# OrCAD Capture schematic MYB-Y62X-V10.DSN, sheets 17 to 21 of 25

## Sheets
17 PAGE18 - USB2.0 HUB #: size A2; note: USB I/F
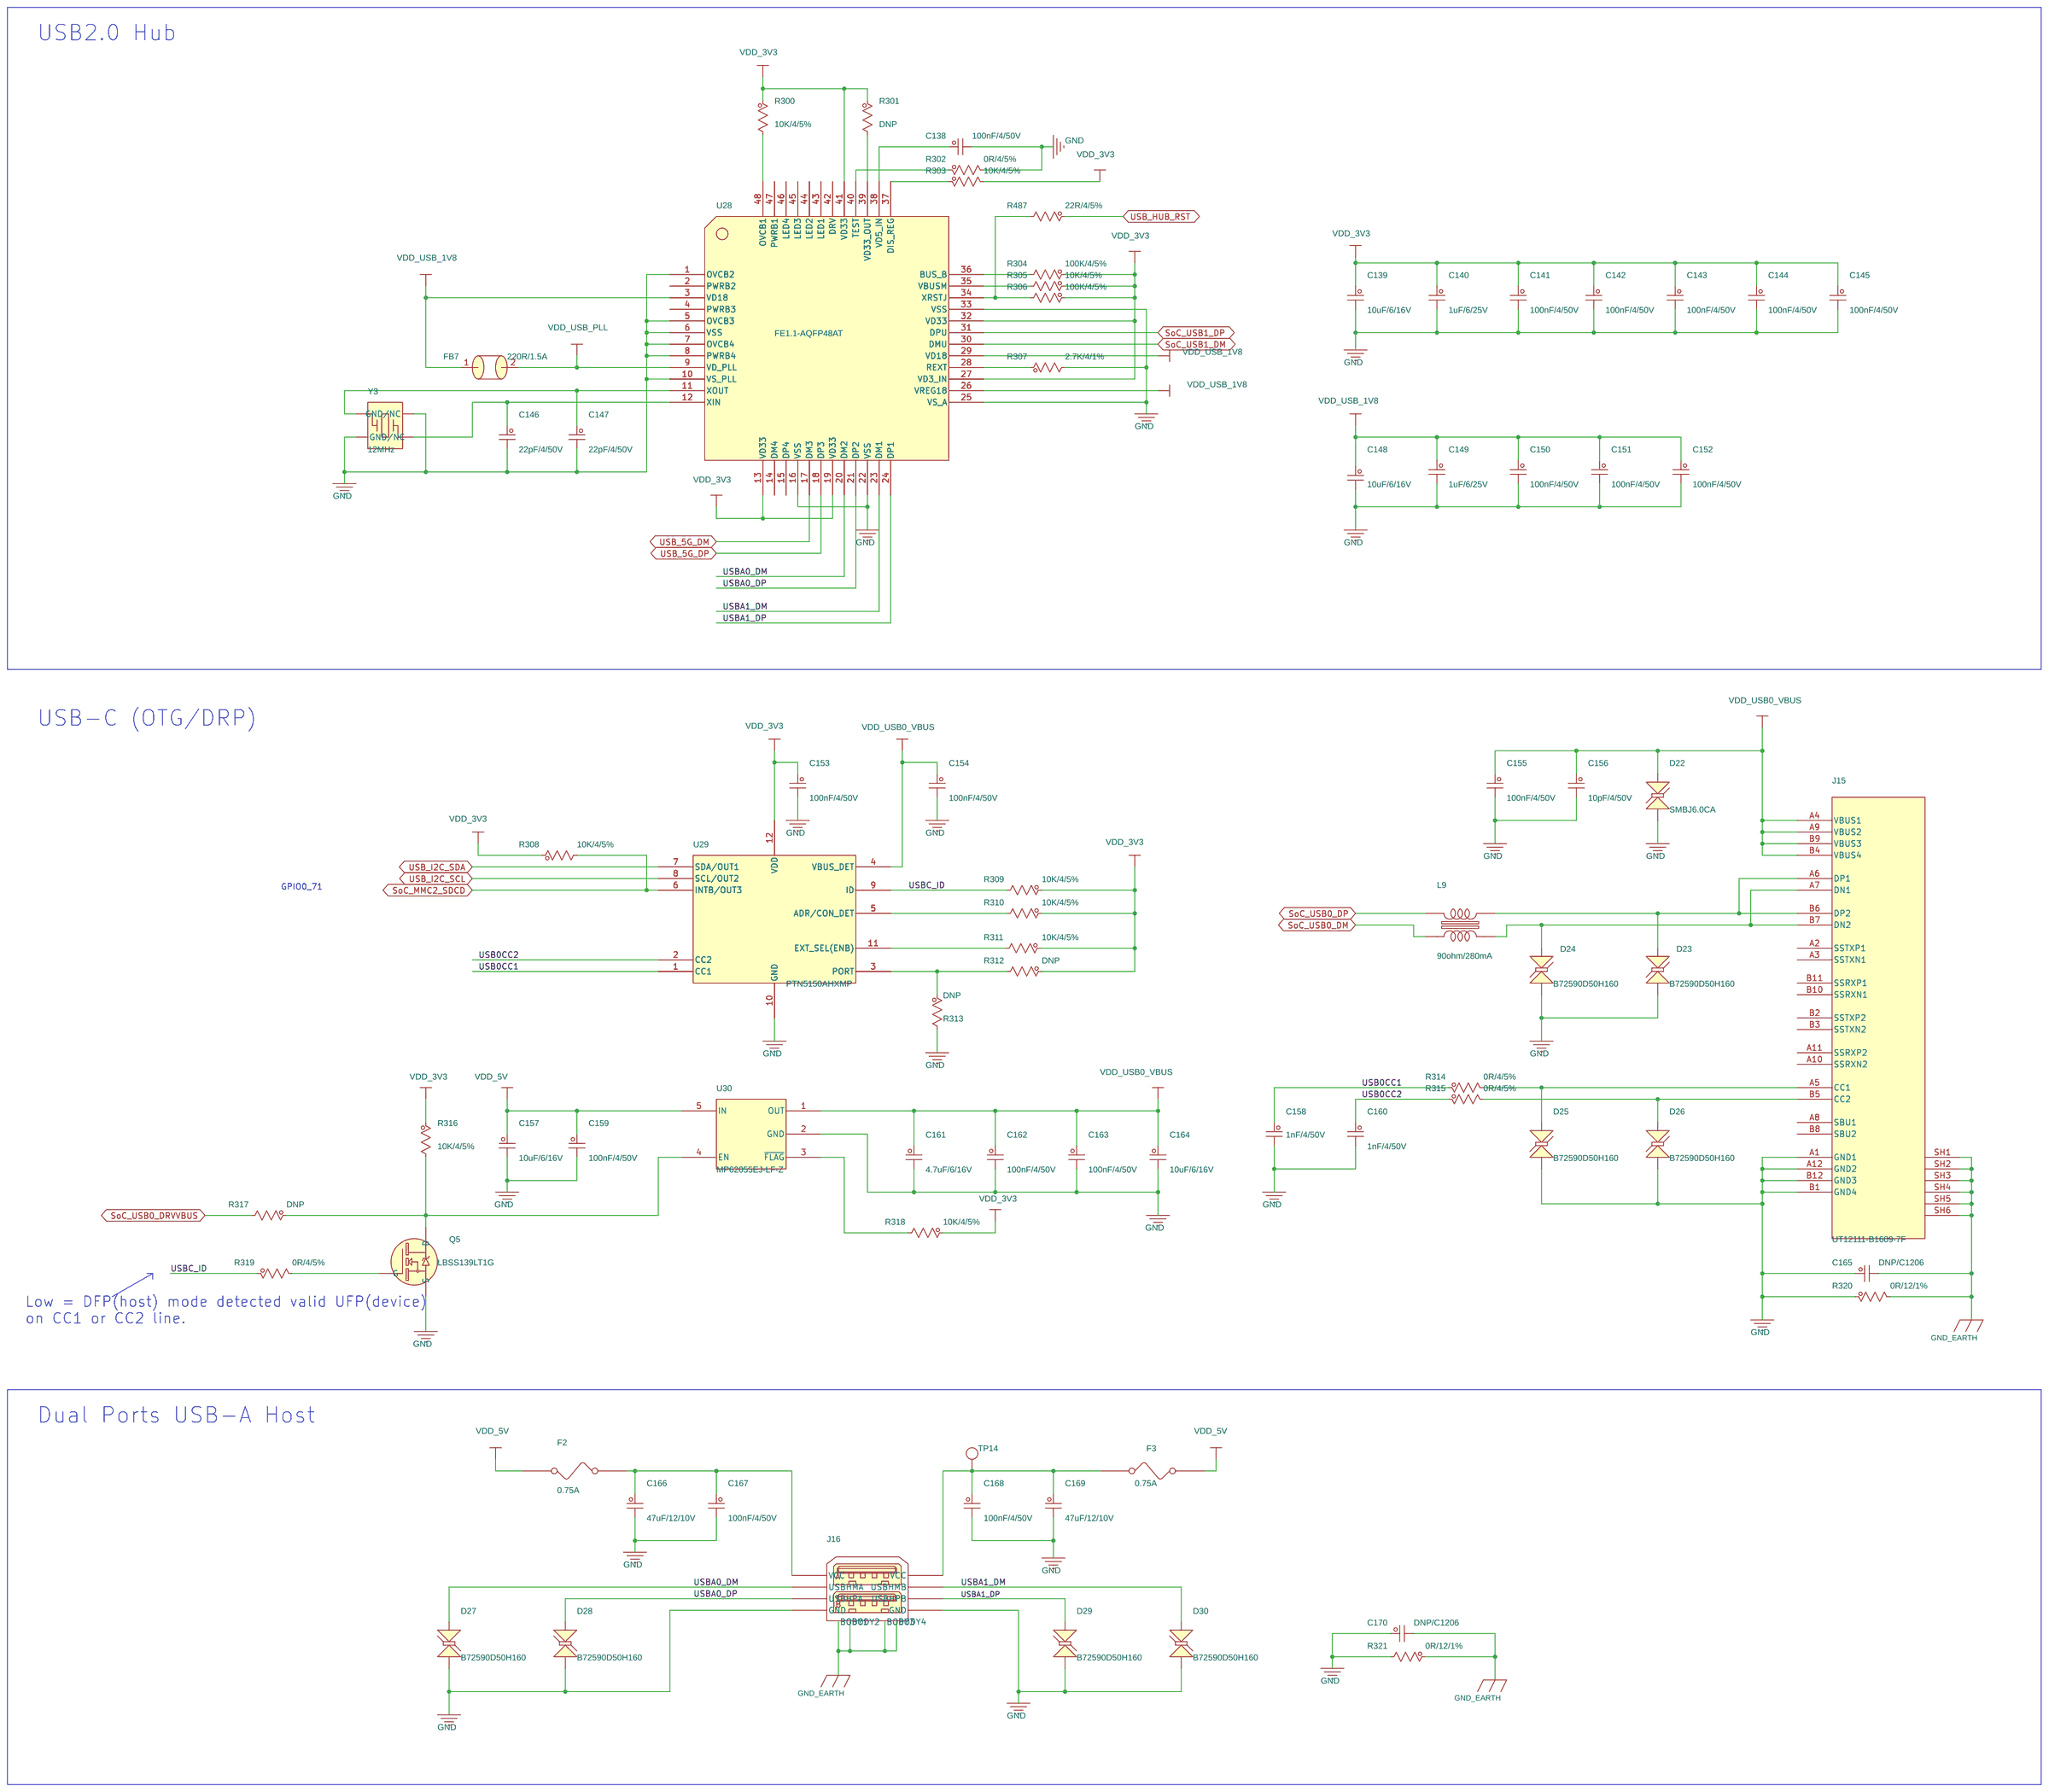
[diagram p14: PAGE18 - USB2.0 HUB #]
18 PAGE20 - RGMII_1 ETHERNET PHY #: size C; note: RGMII_1 ETHERNET PHY
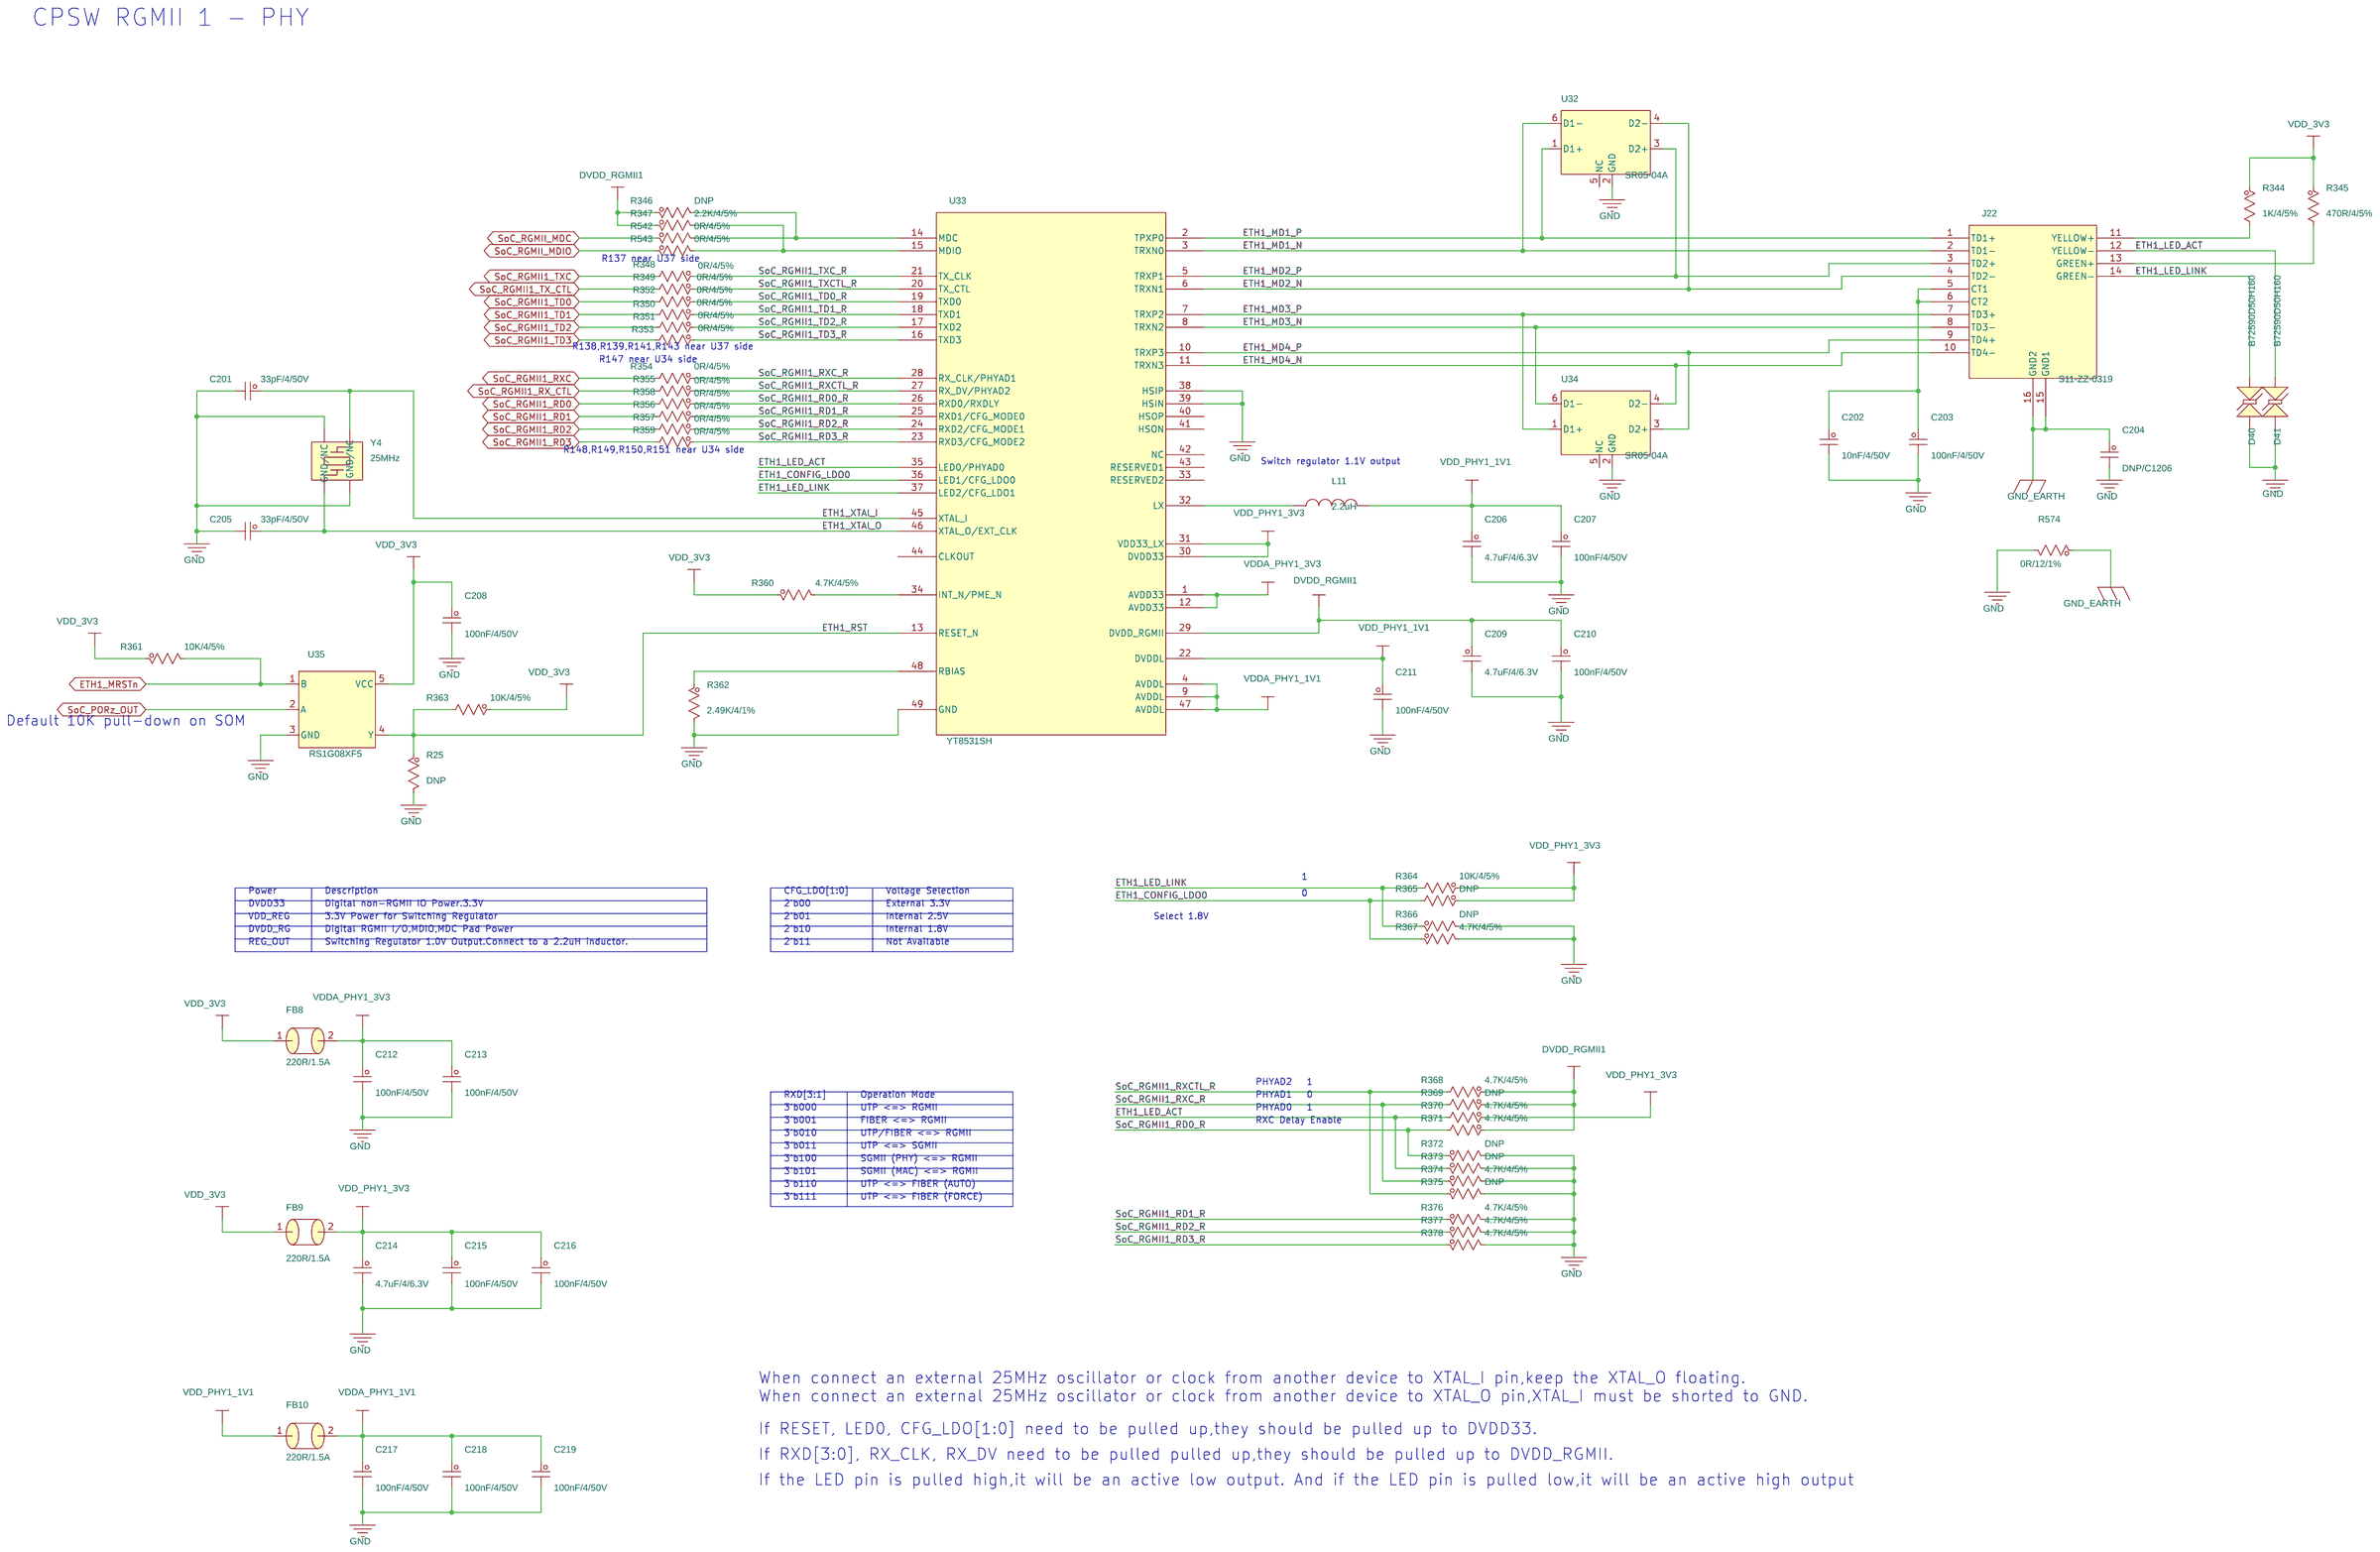
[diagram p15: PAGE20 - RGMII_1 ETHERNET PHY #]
19 PAGE21 - RGMII_2 ETHERNET PHY #: size C; note: RGMII_2 ETHERNET PHY
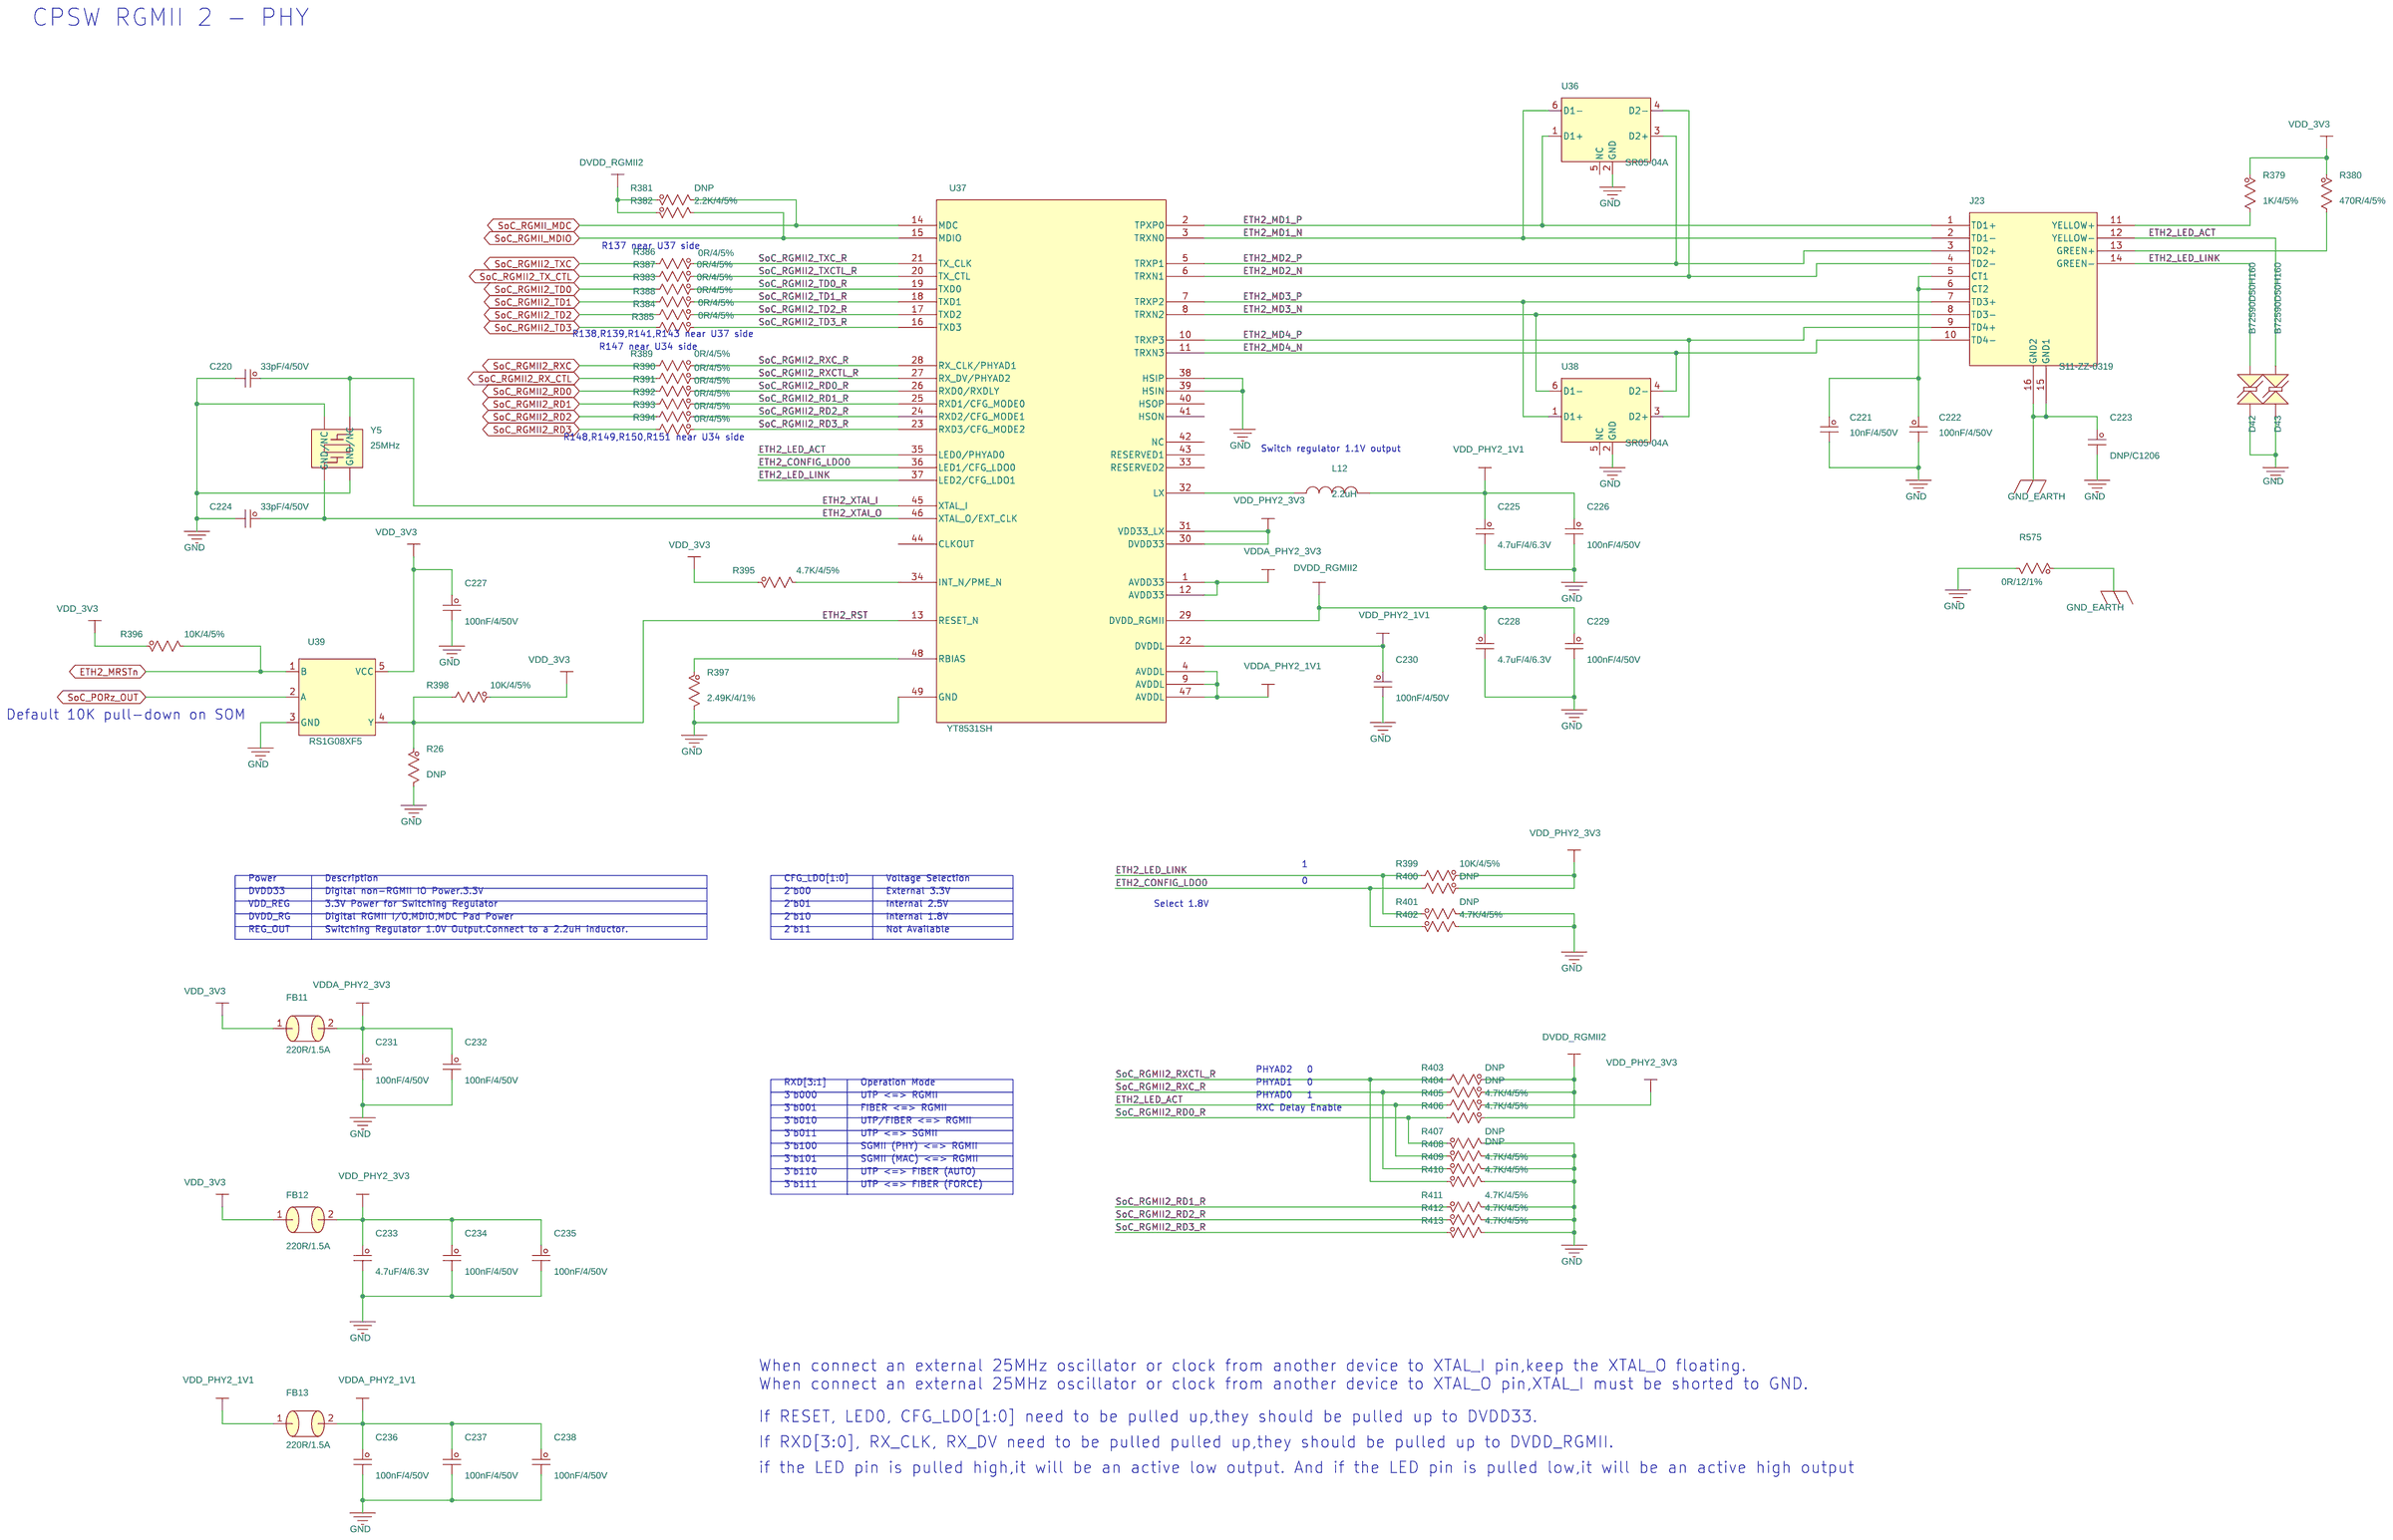
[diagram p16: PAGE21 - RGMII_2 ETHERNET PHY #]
20 PAGE22 - KEY & RTC #: size A3; note: KEY & RTC & PH-RPI
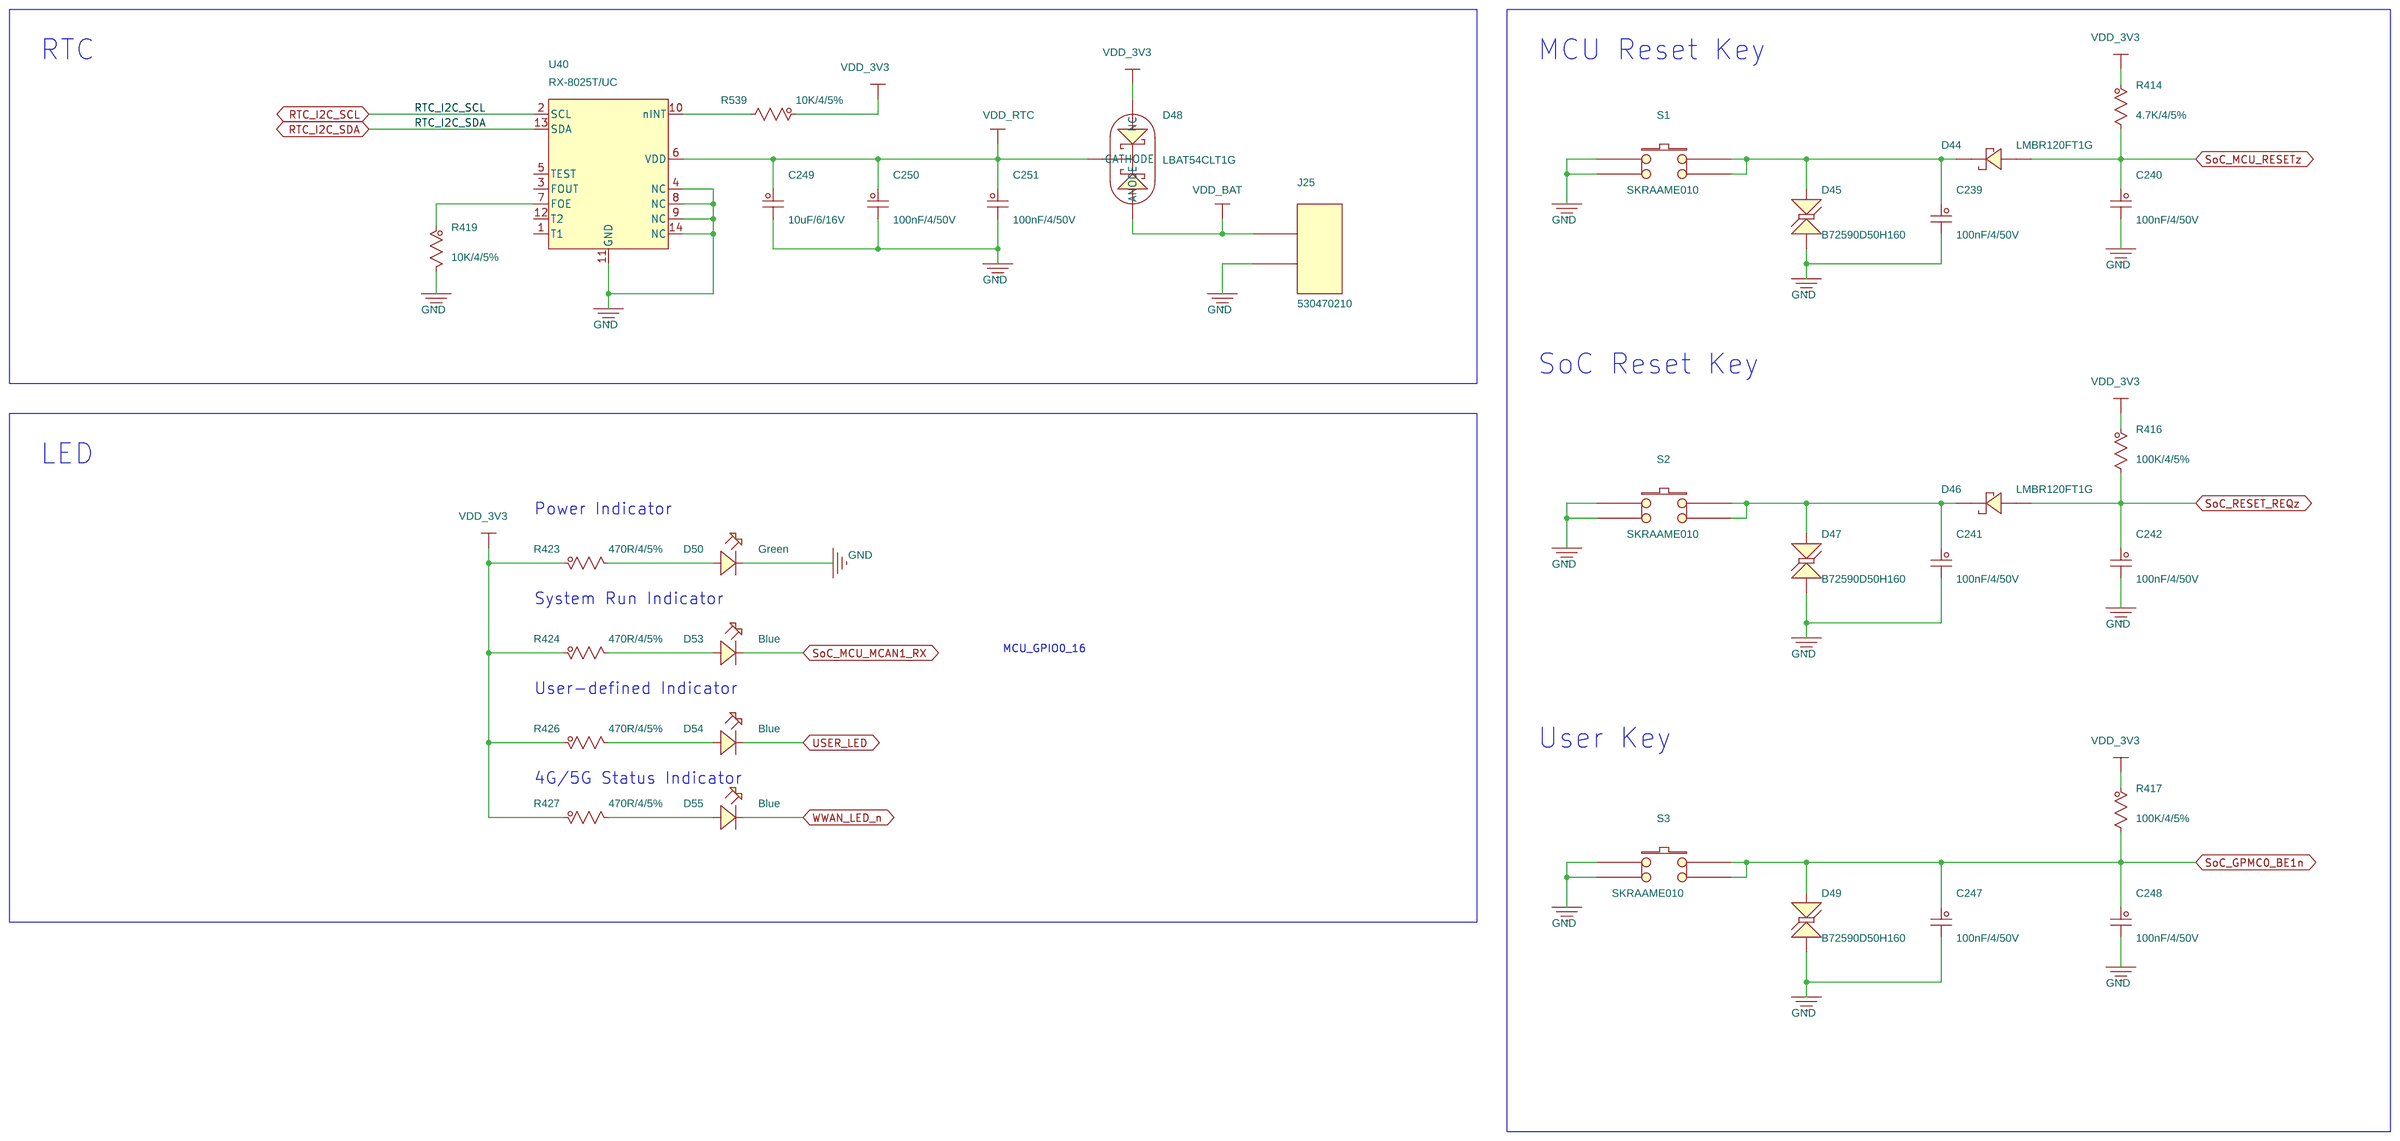
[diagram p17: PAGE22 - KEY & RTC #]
21 PAGE23 - IO EXPANDER #: size C; note: IO EXPANDER
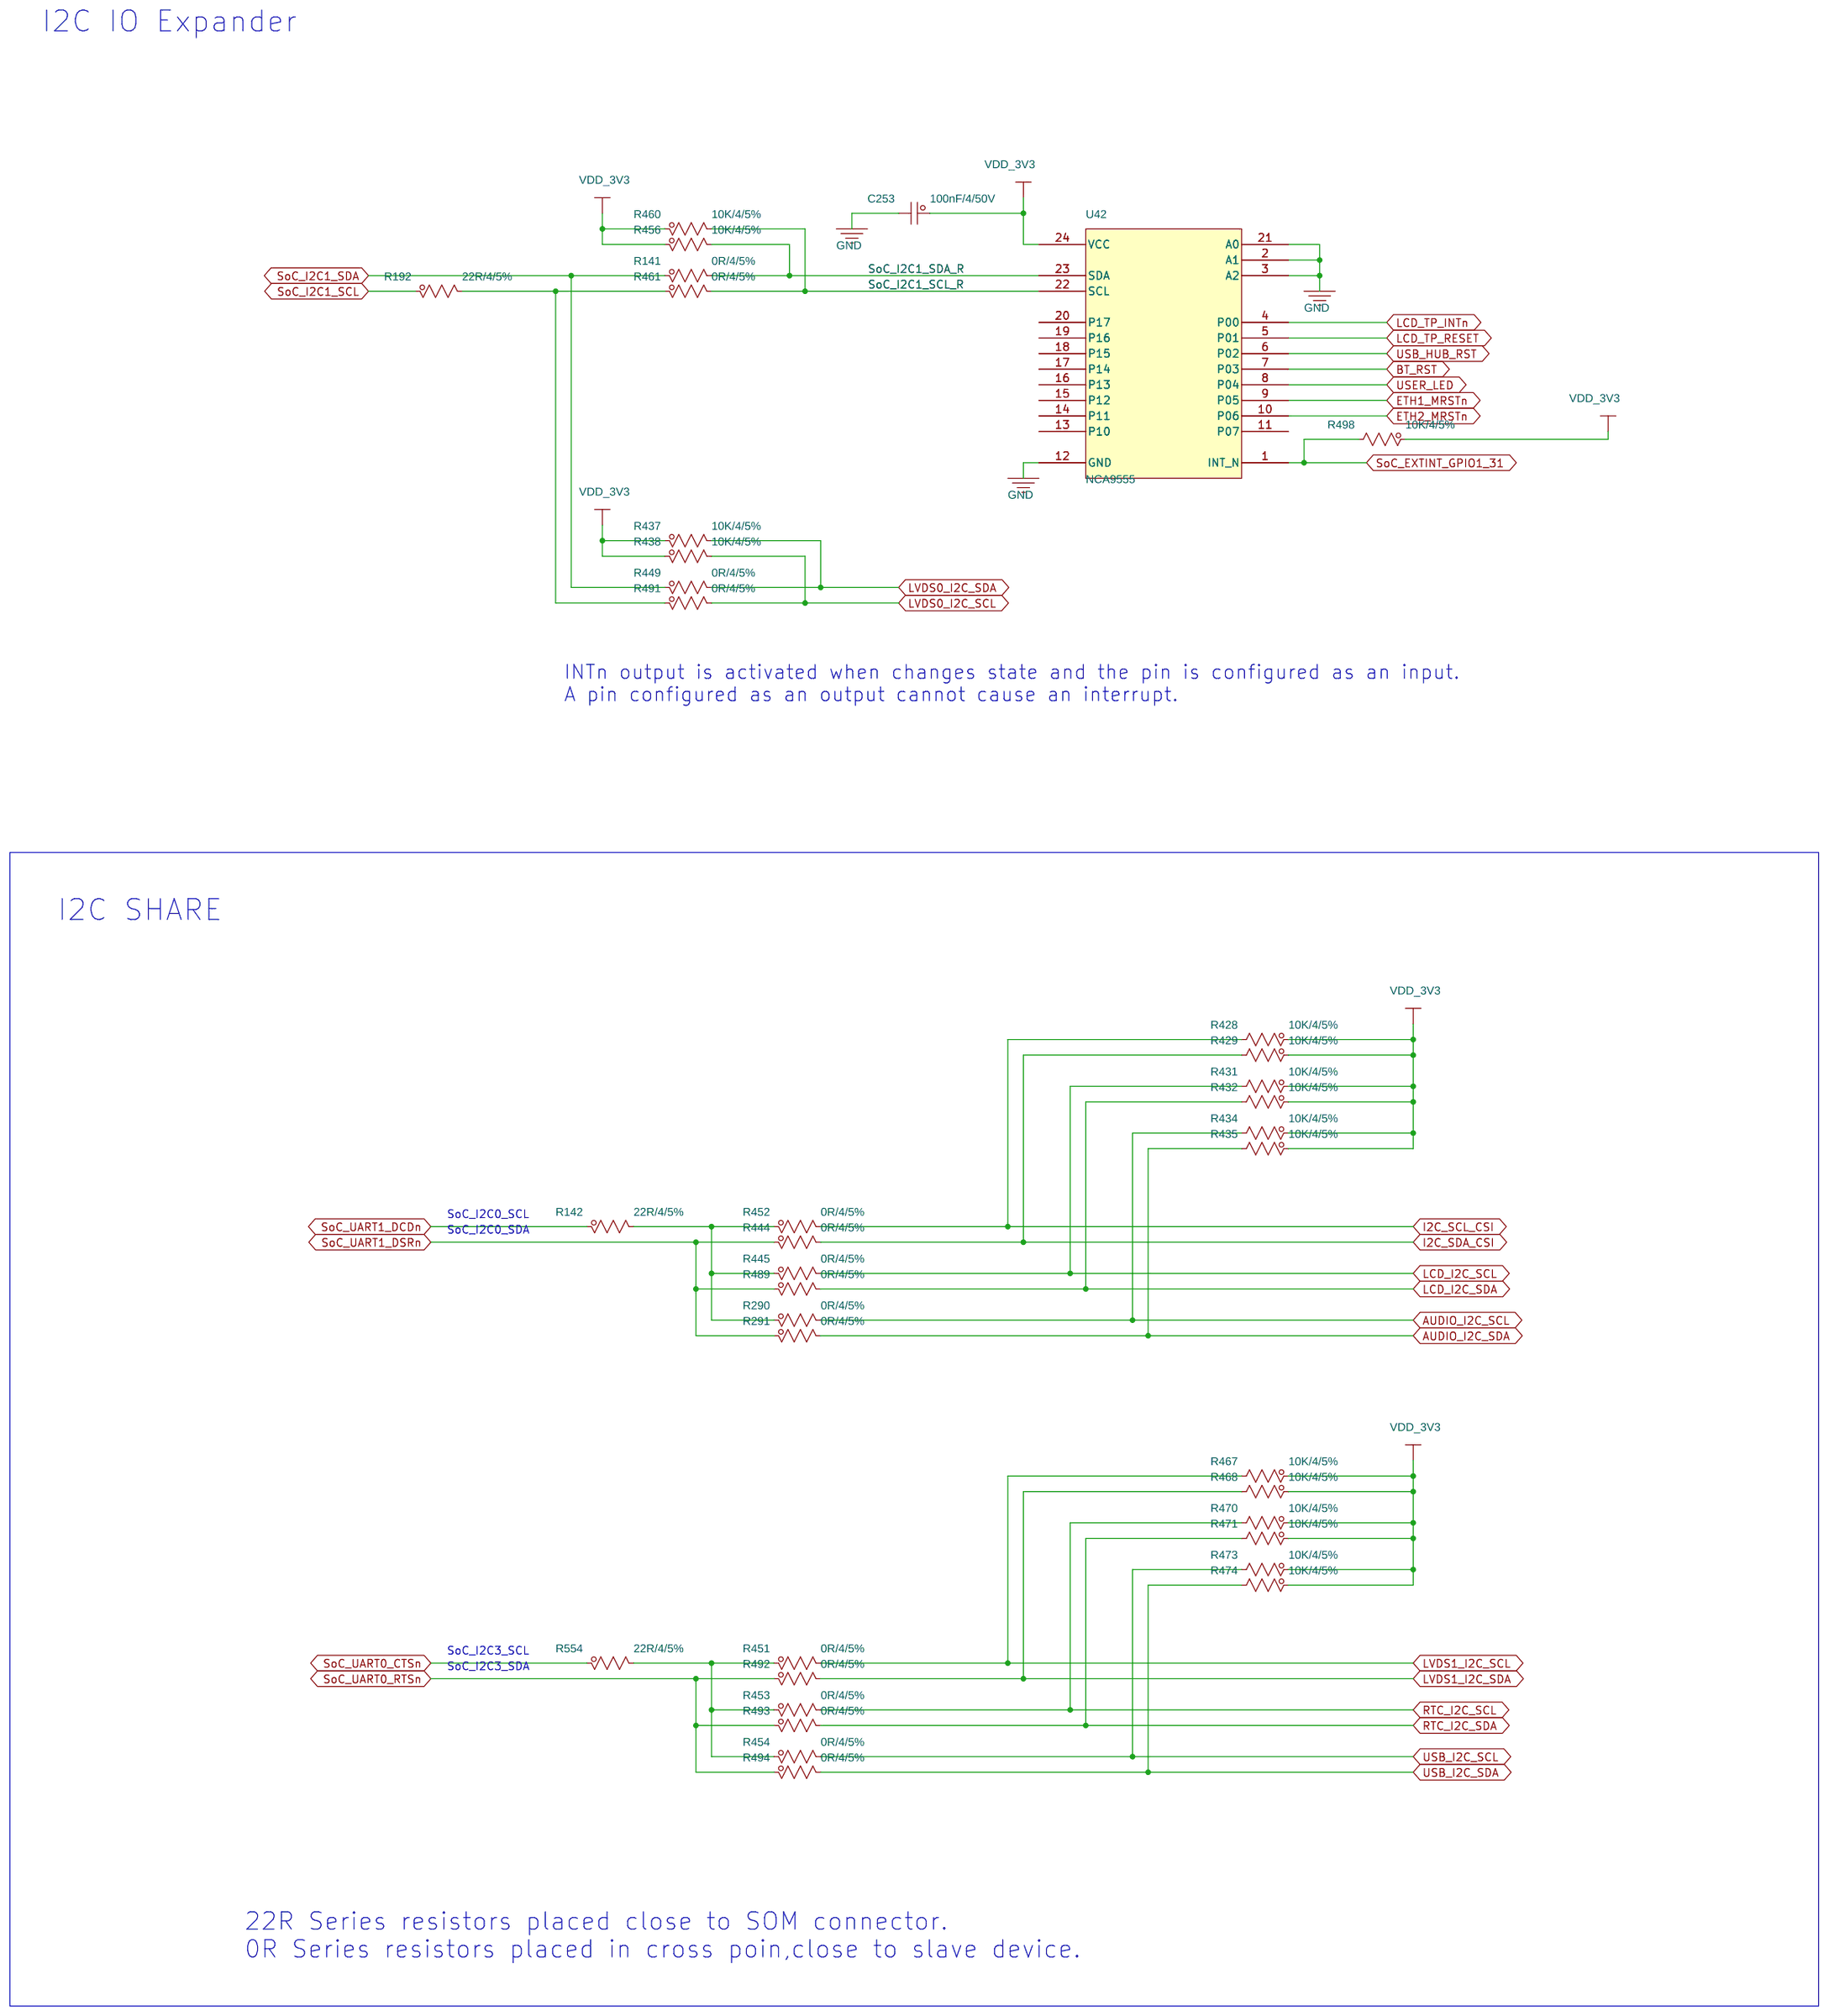
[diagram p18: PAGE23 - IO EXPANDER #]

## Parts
sheet PAGE18 - USB2.0 HUB #
C138  100nF/4/50V  [C0402]
C139  10uF/6/16V  [C0603]
C140  1uF/6/25V  [C0603]
C141  100nF/4/50V  [C0402]
C142  100nF/4/50V  [C0402]
C143  100nF/4/50V  [C0402]
C144  100nF/4/50V  [C0402]
C145  100nF/4/50V  [C0402]
C146  22pF/4/50V  [C0402]
C147  22pF/4/50V  [C0402]
C148  10uF/6/16V  [C0603]
C149  1uF/6/25V  [C0603]
C150  100nF/4/50V  [C0402]
C151  100nF/4/50V  [C0402]
C152  100nF/4/50V  [C0402]
C153  100nF/4/50V  [C0402]
C154  100nF/4/50V  [C0402]
C155  100nF/4/50V  [C0402]
C156  10pF/4/50V  [C0402]
C157  10uF/6/16V  [C0603]
C158  1nF/4/50V  [C0402]
C159  100nF/4/50V  [C0402]
C160  1nF/4/50V  [C0402]
C161  4.7uF/6/16V  [C0603]
C162  100nF/4/50V  [C0402]
C163  100nF/4/50V  [C0402]
C164  10uF/6/16V  [C0603]
C165  DNP/C1206  [C1206]
C166  47uF/12/10V  [C1206]
C167  100nF/4/50V  [C0402]
C168  100nF/4/50V  [C0402]
C169  47uF/12/10V  [C1206]
C170  DNP/C1206  [C1206]
D22  SMBJ6.0CA  [DO-214AA]
D23  B72590D50H160  [D0402]
D24  B72590D50H160  [D0402]
D25  B72590D50H160  [D0402]
D26  B72590D50H160  [D0402]
D27  B72590D50H160  [D0402]
D28  B72590D50H160  [D0402]
D29  B72590D50H160  [D0402]
D30  B72590D50H160  [D0402]
F2  0.75A  [F1206]
F3  0.75A  [F1206]
FB7  220R/1.5A  [FB0603]
J15  UT12111-B1609-7F  [UT12111-B1609-7F]
J16  UB11121-8FDE-4F  [UB11121-8FDE-4F]
L9  90ohm/280mA  [indcm-sdcw2012]
Q5  LBSS139LT1G  [SOT-23]
R300  10K/4/5%  [R0402]
R301  DNP  [R0402]
R302  0R/4/5%  [R0402]
R303  10K/4/5%  [R0402]
R304  100K/4/5%  [R0402]
R305  10K/4/5%  [R0402]
R306  100K/4/5%  [R0402]
R307  2.7K/4/1%  [R0402]
R308  10K/4/5%  [R0402]
R309  10K/4/5%  [R0402]
R310  10K/4/5%  [R0402]
R311  10K/4/5%  [R0402]
R312  DNP  [R0402]
R313  DNP  [R0402]
R314  0R/4/5%  [R0402]
R315  0R/4/5%  [R0402]
R316  10K/4/5%  [R0402]
R317  DNP  [R0402]
R318  10K/4/5%  [R0402]
R319  0R/4/5%  [R0402]
R320  0R/12/1%  [R1206]
R321  0R/12/1%  [R1206]
R487  22R/4/5%  [R0402]
TP14  SMD  [test0_8-smd]
U28  FE1.1-AQFP48AT  [LQFP48]
U29  PTN5150AHXMP  [x2qfn12]
U30  MP62055EJ-LF-Z  [SOT23-5]
Y3  12MHz  [3225]
sheet PAGE20 - RGMII_1 ETHERNET PHY #
C201  33pF/4/50V  [C0402]
C202  10nF/4/50V  [C0402]
C203  100nF/4/50V  [C0402]
C204  DNP/C1206  [C1206]
C205  33pF/4/50V  [C0402]
C206  4.7uF/4/6.3V  [C0402]
C207  100nF/4/50V  [C0402]
C208  100nF/4/50V  [C0402]
C209  4.7uF/4/6.3V  [C0402]
C210  100nF/4/50V  [C0402]
C211  100nF/4/50V  [C0402]
C212  100nF/4/50V  [C0402]
C213  100nF/4/50V  [C0402]
C214  4.7uF/4/6.3V  [C0402]
C215  100nF/4/50V  [C0402]
C216  100nF/4/50V  [C0402]
C217  100nF/4/50V  [C0402]
C218  100nF/4/50V  [C0402]
C219  100nF/4/50V  [C0402]
D40  B72590D50H160  [D0402]
D41  B72590D50H160  [D0402]
FB8  220R/1.5A  [FB0603]
FB9  220R/1.5A  [FB0603]
FB10  220R/1.5A  [FB0603]
J22  S11-ZZ-0319  [S11-ZZ-0319]
L11  2.2uH  [L3X3]
R25  DNP  [R0402]
R344  1K/4/5%  [R0402]
R345  470R/4/5%  [R0402]
R346  DNP  [R0402]
R347  2.2K/4/5%  [R0402]
R348  0R/4/5%  [R0402]
R349  0R/4/5%  [R0402]
R350  0R/4/5%  [R0402]
R351  0R/4/5%  [R0402]
R352  0R/4/5%  [R0402]
R353  0R/4/5%  [R0402]
R354  0R/4/5%  [R0402]
R355  0R/4/5%  [R0402]
R356  0R/4/5%  [R0402]
R357  0R/4/5%  [R0402]
R358  0R/4/5%  [R0402]
R359  0R/4/5%  [R0402]
R360  4.7K/4/5%  [R0402]
R361  10K/4/5%  [R0402]
R362  2.49K/4/1%  [R0402]
R363  10K/4/5%  [R0402]
R364  10K/4/5%  [R0402]
R365  DNP  [R0402]
R366  DNP  [R0402]
R367  4.7K/4/5%  [R0402]
R368  4.7K/4/5%  [R0402]
R369  DNP  [R0402]
R370  4.7K/4/5%  [R0402]
R371  4.7K/4/5%  [R0402]
R372  DNP  [R0402]
R373  DNP  [R0402]
R374  4.7K/4/5%  [R0402]
R375  DNP  [R0402]
R376  4.7K/4/5%  [R0402]
R377  4.7K/4/5%  [R0402]
R378  4.7K/4/5%  [R0402]
R542  0R/4/5%  [R0402]
R543  0R/4/5%  [R0402]
R574  0R/12/1%  [R1206]
U32  SR05-04A  [SOT23-6]
U33  YT8531SH  [QFN48-0_4]
U34  SR05-04A  [SOT23-6]
U35  RS1G08XF5  [SOT23-5]
Y4  25MHz  [3225]
sheet PAGE21 - RGMII_2 ETHERNET PHY #
C220  33pF/4/50V  [C0402]
C221  10nF/4/50V  [C0402]
C222  100nF/4/50V  [C0402]
C223  DNP/C1206  [C1206]
C224  33pF/4/50V  [C0402]
C225  4.7uF/4/6.3V  [C0402]
C226  100nF/4/50V  [C0402]
C227  100nF/4/50V  [C0402]
C228  4.7uF/4/6.3V  [C0402]
C229  100nF/4/50V  [C0402]
C230  100nF/4/50V  [C0402]
C231  100nF/4/50V  [C0402]
C232  100nF/4/50V  [C0402]
C233  4.7uF/4/6.3V  [C0402]
C234  100nF/4/50V  [C0402]
C235  100nF/4/50V  [C0402]
C236  100nF/4/50V  [C0402]
C237  100nF/4/50V  [C0402]
C238  100nF/4/50V  [C0402]
D42  B72590D50H160  [D0402]
D43  B72590D50H160  [D0402]
FB11  220R/1.5A  [FB0603]
FB12  220R/1.5A  [FB0603]
FB13  220R/1.5A  [FB0603]
J23  S11-ZZ-0319  [S11-ZZ-0319]
L12  2.2uH  [L3X3]
R26  DNP  [R0402]
R379  1K/4/5%  [R0402]
R380  470R/4/5%  [R0402]
R381  DNP  [R0402]
R382  2.2K/4/5%  [R0402]
R383  0R/4/5%  [R0402]
R384  0R/4/5%  [R0402]
R385  0R/4/5%  [R0402]
R386  0R/4/5%  [R0402]
R387  0R/4/5%  [R0402]
R388  0R/4/5%  [R0402]
R389  0R/4/5%  [R0402]
R390  0R/4/5%  [R0402]
R391  0R/4/5%  [R0402]
R392  0R/4/5%  [R0402]
R393  0R/4/5%  [R0402]
R394  0R/4/5%  [R0402]
R395  4.7K/4/5%  [R0402]
R396  10K/4/5%  [R0402]
R397  2.49K/4/1%  [R0402]
R398  10K/4/5%  [R0402]
R399  10K/4/5%  [R0402]
R400  DNP  [R0402]
R401  DNP  [R0402]
R402  4.7K/4/5%  [R0402]
R403  DNP  [R0402]
R404  DNP  [R0402]
R405  4.7K/4/5%  [R0402]
R406  4.7K/4/5%  [R0402]
R407  DNP  [R0402]
R408  DNP  [R0402]
R409  4.7K/4/5%  [R0402]
R410  4.7K/4/5%  [R0402]
R411  4.7K/4/5%  [R0402]
R412  4.7K/4/5%  [R0402]
R413  4.7K/4/5%  [R0402]
R575  0R/12/1%  [R1206]
U36  SR05-04A  [SOT23-6]
U37  YT8531SH  [QFN48-0_4]
U38  SR05-04A  [SOT23-6]
U39  RS1G08XF5  [SOT23-5]
Y5  25MHz  [3225]
sheet PAGE22 - KEY & RTC #
C239  100nF/4/50V  [C0402]
C240  100nF/4/50V  [C0402]
C241  100nF/4/50V  [C0402]
C242  100nF/4/50V  [C0402]
C247  100nF/4/50V  [C0402]
C248  100nF/4/50V  [C0402]
C249  10uF/6/16V  [C0603]
C250  100nF/4/50V  [C0402]
C251  100nF/4/50V  [C0402]
D44  LMBR120FT1G  [SOD123]
D45  B72590D50H160  [D0402]
D46  LMBR120FT1G  [SOD123]
D47  B72590D50H160  [D0402]
D48  LBAT54CLT1G  [SOT-23]
D49  B72590D50H160  [D0402]
D50  Green  [LED0603]
D53  Blue  [LED0603]
D54  Blue  [LED0603]
D55  Blue  [LED0603]
J25  530470210  [CONN1x2-1_25-dip]
R414  4.7K/4/5%  [R0402]
R416  100K/4/5%  [R0402]
R417  100K/4/5%  [R0402]
R419  10K/4/5%  [R0402]
R423  470R/4/5%  [R0402]
R424  470R/4/5%  [R0402]
R426  470R/4/5%  [R0402]
R427  470R/4/5%  [R0402]
R539  10K/4/5%  [R0402]
S1  SKRAAME010  [SKRAAME010]
S2  SKRAAME010  [SKRAAME010]
S3  SKRAAME010  [SKRAAME010]
U40  RX-8025T/UC  [SOP14]
sheet PAGE23 - IO EXPANDER #
C253  100nF/4/50V  [C0402]
R141  0R/4/5%  [R0402]
R142  22R/4/5%  [R0402]
R192  22R/4/5%  [R0402]
R290  0R/4/5%  [R0402]
R291  0R/4/5%  [R0402]
R428  10K/4/5%  [R0402]
R429  10K/4/5%  [R0402]
R431  10K/4/5%  [R0402]
R432  10K/4/5%  [R0402]
R434  10K/4/5%  [R0402]
R435  10K/4/5%  [R0402]
R437  10K/4/5%  [R0402]
R438  10K/4/5%  [R0402]
R444  0R/4/5%  [R0402]
R445  0R/4/5%  [R0402]
R449  0R/4/5%  [R0402]
R451  0R/4/5%  [R0402]
R452  0R/4/5%  [R0402]
R453  0R/4/5%  [R0402]
R454  0R/4/5%  [R0402]
R456  10K/4/5%  [R0402]
R460  10K/4/5%  [R0402]
R461  0R/4/5%  [R0402]
R467  10K/4/5%  [R0402]
R468  10K/4/5%  [R0402]
R470  10K/4/5%  [R0402]
R471  10K/4/5%  [R0402]
R473  10K/4/5%  [R0402]
R474  10K/4/5%  [R0402]
R489  0R/4/5%  [R0402]
R491  0R/4/5%  [R0402]
R492  0R/4/5%  [R0402]
R493  0R/4/5%  [R0402]
R494  0R/4/5%  [R0402]
R498  10K/4/5%  [R0402]
R554  22R/4/5%  [R0402]
U42  NCA9555  [TSSOP24]

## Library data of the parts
C138 C141-C145 C150-C155 C159 C162 C163 C167 C168 C203 C207 C208 C210-C213 C215-C219 C222 C226 C227 C229-C232 C234-C242 C247 C248 C250 C251 C253 = Ceramic_Capacitor: Ceramic Capacitor,100nF,50V,+/-10%,X7R,0402,Fenghua; Manufacturer: Fenghua; Manufacturer P/N: 0402B104K500NT; Myir P/N: 20401.80111; Part Type: Ceramic Capacitor; Reserve Value: 100nF; Datasheet: FENGHUA-Capacitor.pdf
C139 C148 C157 C164 C249 = Ceramic_Capacitor: Ceramic Capacitor,10uF,16V,+/-20%,X5R,0603,Samsung; Manufacturer: Samsung; Manufacturer P/N: CL10A106MO8NQNC; Myir P/N: 20401.80062; Part Type: Ceramic Capacitor; Reserve Value: 10uF; Datasheet: Samsung.pdf
C140 C149 = Ceramic_Capacitor: Ceramic Capacitor,1uF, 25V,+/-10%,X5R,0603,Samsung; Manufacturer: Samsung; Manufacturer P/N: CL10A105KA8NNNC; Myir P/N: 20401.80063; Part Type: Ceramic Capacitor; Reserve Value: 1uF; Datasheet: Samsung.pdf
C146 C147 = Ceramic_Capacitor: Ceramic Capacitor,22pF,50V,+/-5%,C0G,0402,Fenghua; Manufacturer: Fenghua; Manufacturer P/N: 0402CG220J500NT; Myir P/N: 20401.80101; Part Type: Ceramic Capacitor; Reserve Value: 22pF; Datasheet: FENGHUA-Capacitor.pdf
C156 = Ceramic_Capacitor: Ceramic Capacitor,10pF,50V,+/-5%,C0G,0402,Fenghua; Manufacturer: Fenghua; Manufacturer P/N: 0402CG100J500NT; Myir P/N: 20401.00076; Part Type: Ceramic Capacitor; Reserve Value: 10pF; Datasheet: FENGHUA-Capacitor.pdf
C158 C160 = Ceramic_Capacitor: Ceramic Capacitor,1nF,50V,+/-10%,X7R,0402,Fenghua; Manufacturer: Fenghua; Manufacturer P/N: 0402B102K500NT; Myir P/N: 20401.80096; Part Type: Ceramic Capacitor; Reserve Value: 1nF; Datasheet: FENGHUA-Capacitor.pdf
C161 = Ceramic_Capacitor: Ceramic Capacitor,4.7uF,16V, +/-10%,X5R,0603,Samsung; Manufacturer: Samsung; Manufacturer P/N: CL10A475KO8NNNC; Myir P/N: 20401.80066; Part Type: Ceramic Capacitor; Reserve Value: 4.7uF; Datasheet: Samsung.pdf
C165 C170 C204 C223 = Ceramic_Capacitor: DNP; Manufacturer: DNP; Manufacturer P/N: DNP; Myir P/N: DNP; Part Type: DNP; Reserve Value: DNP; Datasheet: DNP
C166 C169 = Ceramic_Capacitor: Ceramic Capacitor,47uF,10V,+/-20%,X5R,1206,Samsung; Manufacturer: Samsung; Manufacturer P/N: CL31A476MPHNNNE; Myir P/N: 20401.80106; Part Type: Ceramic Capacitor; Reserve Value: 47uF; Datasheet: Samsung.pdf
D22 = TVS_Diode: Diode, TVS Bi-Dir 6V 600W, DO-214AA(SMB); Manufacturer: UN; Myir P/N: 20701.00028; Part Type: Diode; Datasheet: SMBJ6.0C.pdf
D23-D30 D40-D43 D45 D47 D49 = TVS_Diode: Diode,TVS,5.6VDC,SMD,D0402,TDK; Manufacturer: TDK; Myir P/N: 20701.00001; Part Type: Diode; Datasheet: B72590D0050H160.pdf
F2 F3 = Fuse: Fuse,Resettable,0.75A,6V,SMD,1206,Bourns; Manufacturer: Bourns; Manufacturer P/N: MF-NSMF075-2; Myir P/N: 20801.00003; Part Type: Resettable Fuse; Datasheet: mfnsmf.pdf
FB7-FB13 = Ferrite_Bead: Ferrite Bead,220R@100Mhz,1.5A,+/-25%,SMD,0603,Fenghua; Manufacturer: Fenghua; Manufacturer P/N: CBM160808U221T; Myir P/N: 20601.80007; Part Type: Ferrite Bead; Reserve Value: 220R; Datasheet: CBM160808U221T.pdf
J15 = UT12111-B1609-7F: Connector,USB C,24Pin,–25℃~＋85℃,SMT,Foxconn; Manufacturer: Foxconn; Myir P/N: 21107.00017; Part Type: USB Connector; Datasheet: USB_C_Foxconn_UT12111-B1609-7F_.pdf
J16 = UB11121-8FDE-4F: Connector,Double-USB A,Female,Right angle,4Pos,4.13mm,1u”MIN Gold Plate,-55~85℃,Foxconn; Manufacturer: Foxconn; Myir P/N: 21121.00004; Part Type: USB Connector; Datasheet: DUSB_A_Foxconn_UB11121-8FDE-4F.pdf
L9 = Common_Choke: Inductor,Common Choke,90ohm@100MHz,±25%,280mA,0.4ohm,SMD 2*1.2*1.2mm,Sunlord; Manufacturer: Sunlord; Manufacturer P/N: SDCW2012-2-900TF; Myir P/N: 20504.00002; Part Type: Common Inductor; Reserve Value: 90ohm; Datasheet: SDCW2012-2.pdf
Q5 = N-MOSFET: Mosfet,N-Channel,50V,0.2A,SMD,SOT-23,LRC; Manufacturer: LRC; Myir P/N: 20703.00012; Part Type: Mosfet; Datasheet: LBSS139LT1G.pdf
R25 R26 R300 R303 R305 R308-R311 R313 R316 R361 R363 R364 R396 R398 R399 R428 R429 R431 R432 R434 R435 R437 R438 R456 R460 R467 R468 R470 R471 R473 R474 R498 R539 = Resister: Thick Film Resistor,10K,+/-5%,1/16W,-55°C ~ 155°C,SMD,0402,Fenghua; Manufacturer: Fenghua; Manufacturer P/N: RC-02W103JT; Myir P/N: 20301.00199; Part Type: Thick Film Resistor; Reserve Value: 10K; Datasheet: FHsheet_2018-07-30.PDF
R141 R290 R291 R301 R302 R314 R315 R317 R444 R445 R449 R451-R454 R461 R489 R491-R494 R543 = Resister: Thick Film Resistor,0R,+/-5%,1/16W,-55°C ~ 155°C,SMD,0402,Fenghua; Manufacturer: Fenghua; Manufacturer P/N: RC-02000JT; Myir P/N: 20301.00186; Part Type: Thick Film Resistor; Reserve Value: 0R; Datasheet: FHsheet_2018-07-30.PDF
R304 R306 R416 R417 = Resister: Thick Film Resistor,100K,+/-5%,,1/16W,-55°C ~ 155°C,SMD,0402,Fenghua; Manufacturer: Fenghua; Manufacturer P/N: RC-02W104JT; Myir P/N: 20301.00210; Part Type: Thick Film Resistor; Reserve Value: 100K; Datasheet: FHsheet_2018-07-30.PDF
R307 = Resister: Thick Film Resistor,2.7K,+/-1%,1/16W,-55°C ~ 155°C,SMD,0402,Fenghua; Manufacturer: Fenghua; Manufacturer P/N: RC-02W2701FT; Myir P/N: 20301.80391; Part Type: Thick Film Resistor; Reserve Value: 2.7K; Datasheet: FHsheet_2018-07-30.PDF
R312 = Resister: Thick Film Resistor,10K,+/-5%,1/16W,-55°C ~ 155°C,SMD,0402,Fenghua; Manufacturer: Fenghua; Manufacturer P/N: RC-02W103JT; Myir P/N: 20301.00199; Part Type: Thick Film Resistor; Reserve Value: 10K; Datasheet: FH规格书_2018-07-30.pdf
R318 R419 = Resister: Thick Film Resistor,10K,+/-5%,1/16W,-55℃~155℃,SMD,0402,Fenghua; Manufacturer: Fenghua; Manufacturer P/N: RC-02W103JT; Myir P/N: 20301.00199; Part Type: Thick Film Resistor; Reserve Value: 10K; Datasheet: FHsheet_2018-07-30.PDF
R319 R348-R359 R383-R394 R542 = Resister: Thick Film Resistor,0R,+/-5%,1/16W,-55℃~155℃,SMD,0402,Fenghua; Manufacturer: Fenghua; Manufacturer P/N: RC-02000JT; Myir P/N: 20301.00186; Part Type: Thick Film Resistor; Reserve Value: 0R; Datasheet: FHsheet_2018-07-30.PDF
R320 R321 R574 R575 = Resister: Thick Film Resistor,0R,+/-1%,1/4W,-55℃~155℃,SMD,1206,Reel,Fenghua; Manufacturer: Fenghua; Manufacturer P/N: RS-06000FT; Myir P/N: 20301.00312; Part Type: Thick Film Resistor; Reserve Value: 0R; Datasheet: FHsheet-20230524.pdf
R142 R192 R487 R554 = Resister: Thick Film Resistor,22R,+/-5%,1/16W,-55°C ~ 155°C,SMD,0402,Fenghua; Manufacturer: Fenghua; Manufacturer P/N: RC-02W220JT; Myir P/N: 20301.00187; Part Type: Thick Film Resistor; Reserve Value: 22R; Datasheet: FHsheet_2018-07-30.PDF
TP14 = TP: DESIG: testing PAD; FAB: NA; REF: NA; VAL: NOT POPULATED
U28 = AQFP48AT: IC,USB 2.0 HIGH SPEED 4-PORT HUB CONTROLLER,LQFP48,SMD,Terminus; Manufacturer: Terminus; Myir P/N: 20107.00076; Part Type: Interface; Datasheet: FE1.1-AQFP48AT.pdf
U29 = PTN5150AHXMP: IC,CC logic for USB Type-C applications,SMD,XFQFN12,50,NXP; Manufacturer: NXP; Myir P/N: 20105.00024; Part Type: Logic; Datasheet: PTN5150.pdf
U30 = MP62055E: IC,Current-Limited, Power-Distribution Switches,SMD,SOT23-5,6G,MPS; Manufacturer: MPS; Manufacturer P/N: MP62055EJ¨CLF¨CZ¨CLF¨CZ; Myir P/N: 20103.00092; Part Type: Power Management; Reserve Value: MP62055EJ¨CLF¨CZ¨CLF¨CZ; Datasheet: MP62055 Rev.1.1.pdf
Y3 = Crystal_4P: Crystal,12MHz,+/-20ppm,18pF,-40~85°C,4Pin,3225,SMD,SJK; Manufacturer: SJK / SJK; Manufacturer P/N: SJK-7U12000MAH2420B8; Myir P/N: 20901.00031; Part Type: Crystal; RP1 Manufacturer P/N: 7M12000031; RP1 Myir P/N: 20901.00003; Datasheet: 7U12000MAH2420B8.pdf
C201 C205 C220 C224 = Ceramic_Capacitor: Ceramic Capacitor,33pF,50V,+/-5%,C0G,0402,Fenghua; Manufacturer: Fenghua; Manufacturer P/N: 0402CG330J500NT; Myir P/N: 20401.00091; Part Type: Ceramic Capacitor; Reserve Value: 33pF; Datasheet: FENGHUA-Capacitor.pdf
C202 C221 = Ceramic_Capacitor: Ceramic Capacitor,10nF,50V,+/-10%,X7R,0402,Fenghua; Manufacturer: Fenghua; Manufacturer P/N: 0402B103K500NT; Myir P/N: 20401.80103; Part Type: Ceramic Capacitor; Reserve Value: 10nF; Datasheet: FENGHUA-Capacitor.pdf
C206 C209 C214 C225 C228 C233 = Ceramic_Capacitor: Ceramic Capacitor,4.7uF,6.3V,+/-20%,X5R,0402,Samsung; Manufacturer: Samsung; Manufacturer P/N: CL05A475MQ5NRNC; Myir P/N: 20401.80098; Part Type: Ceramic Capacitor; Reserve Value: 4.7uF; Datasheet: Samsung.pdf
J22 J23 = S11-ZZ-0319: Connector,RJ45 1X1,10/100/1000 Base-T,LED:L-Green; R-Yellow,Gold Flash,-40 °C~+85°C,UDE; Manufacturer: UDE; Myir P/N: 21118.00010; Part Type: ETH Connector; Datasheet: RJ45-UDE_S11-ZZ-0319(20130-00)-A.pdf
L11 L12 = Inductor: Power Inductor,2.2uH,+/-20,SPH,3.0*3.0*1.2mm,SMD,Sunlord; Manufacturer: Sunlord; Manufacturer P/N: SPH3012H2R2MT; Myir P/N: 20501.00034; Part Type: Power Inductor; Datasheet: SPH series of SMD Power Inductor.pdf
R344 R379 = Resister: Thick Film Resistor,1K,+/-5%,1/16W,-55°C ~ 155°C,SMD,0402,Fenghua; Manufacturer: Fenghua; Manufacturer P/N: RC-02W102JT; Myir P/N: 20301.80389; Part Type: Thick Film Resistor; Reserve Value: 1K; Datasheet: FHsheet_2018-07-30.PDF
R345 R380 R423 R424 R426 R427 = Resister: Thick Film Resistor,470R,+/-5%,1/16W,-55°C ~ 155°C,SMD,0402,Fenghua; Manufacturer: Fenghua; Manufacturer P/N: RC-02W471JT; Myir P/N: 20301.00193; Part Type: Thick Film Resistor; Reserve Value: 470R; Datasheet: FHsheet_2018-07-30.PDF
R346 R347 R381 R382 = Resister: Thick Film Resistor,2.2K,+/-5%,1/16W,-55°C ~ 155°C,SMD,0402,Fenghua; Manufacturer: Fenghua; Manufacturer P/N: RC-02W222JT; Myir P/N: 20301.00195; Part Type: Thick Film Resistor; Reserve Value: 2.2K; Datasheet: FHsheet_2018-07-30.PDF
R360 R365-R378 R395 R400-R409 R411-R414 = Resister: Thick Film Resistor,4.7K,+/-5%,1/16W,-55°C ~ 155°C,SMD,0402,Fenghua; Manufacturer: Fenghua; Manufacturer P/N: RC-02W472JT; Myir P/N: 20301.80393; Part Type: Thick Film Resistor; Reserve Value: 4.7K; Datasheet: FHsheet_2018-07-30.PDF
R362 R397 = Resister: Thick Film Resistor,2.49K,+/- 1%,1/16W,-55°C ~ 155°C,SMD,0402,Fenghua; Manufacturer: Fenghua; Manufacturer P/N: RC-02W2491FT; Myir P/N: 20301.00249; Part Type: Thick Film Resistor; Reserve Value: 2.49K; Datasheet: FHsheet_2018-07-30.PDF
U32 U34 U36 U38 = TPD4E1U06: IC,Quad-Channel,High-Speed ESD Protection Device,SMD,SOT23-6,UN; Manufacturer: UN; Myir P/N: 20114.00013; Part Type: Protection; RP1 Manufacturer P/N: TPD4E1U06DBVR; RP1 Myir P/N: 20114.00004; Datasheet: SR05-04A.pdf
U33 U37 = YT8521SH: IC,Ethernet Physical Layer Transceiver,Industrial,10/100/1000M,-40℃~+85℃,SMD,QFN48,Motorcomm; Manufacturer: Motorcomm; Myir P/N: 20107.80039; Part Type: Interface; Datasheet: YT8531SH_YT8531SC_Datasheet_draft.pdf
U35 U39 = 74LVC1G08GW: IC,Single 2-Input Positive-AND Gate,SMD,SOT23-5,Runic; Manufacturer: Runic; Myir P/N: 20105.00034; Part Type: Logic; Datasheet: RS1G08XF5.pdf
Y4 Y5 = Crystal_4P: Crystal,25MHz,+/-10ppm,18pF,4Pin,3225,-40℃to+85℃,SMD,SJK; Manufacturer: SJK; Manufacturer P/N: SJK-7U25000MAH1430B8; Myir P/N: 20901.00029; Part Type: Crystal; RP1 Manufacturer P/N: 7V25000025; RP1 Myir P/N: 20901.00005; RP2 Manufacturer P/N: E3FB25E000012E; RP2 Myir P/N: 20901.00020; Datasheet: 7U25000MAH1430B8.pdf
R410 = Resister: Thick Film Resistor,4.7K,+/-5%,1/16W,-55℃~155℃,SMD,0402,Fenghua; Manufacturer: Fenghua; Manufacturer P/N: RC-02W472JT; Myir P/N: 20301.80393; Part Type: Thick Film Resistor; Reserve Value: 4.7K; Datasheet: FHsheet_2018-07-30.PDF
D44 D46 = Schottky_Diode: Diode,Schottky Barrier Diode,20V,1A,SMD,SOD123L,LRC; Manufacturer: LRC; Myir P/N: 20701.00053; Part Type: Diode; RP1 Manufacturer P/N: MBR120VLSFT1G; RP1 Myir P/N: 20701.00004; Datasheet: LMBR120FT1G.pdf
D48 = BAT54C: Diode Dual Schottky,30V,200mA,SMD,SOT-23,LRC; Manufacturer: LRC; Myir P/N: 20701.00054; Part Type: Diode; RP1 Manufacturer P/N: BAT54CLT1G; RP1 Myir P/N: 20701.00019; Datasheet: LBAT54CLT1G.pdf
D50 = LED-204-10SURD_S530-A3-L: LED,Brilliant Green,Water Clear,25mA,SMD,0603,Everlight,Everlight; Manufacturer: Everlight; Manufacturer P/N: 19-217/G7C-AN1P2-3T; Myir P/N: 20704.80031; Part Type: LED; Datasheet: 19-217-G7C-AN1P2-3T.pdf
D53-D55 = LED-19-217_BHC-ZL1M2RY_3T: LED,Brilliant Blue,Water Clear,10mA,SMD,0603,Everlight; Manufacturer: Everlight; Manufacturer P/N: 19-217/BHC-ZL1M2RY/3T; Myir P/N: 20704.00011; Part Type: LED; Datasheet: 19-217-BHC-ZL1M2RY-3T.pdf
J25 = 1X2PIN: Board Connector,2 Pin,1.25 mm,1 Row(s), Male, Straight,-40 ~ +85 °C,Molex; Manufacturer: Molex; Myir P/N: 21110.00022; Part Type: Board Connector; Datasheet: RTC_conn_Molex_530470210.pdf
S1-S3 = SKRAAME010: Key,6.2mm Square with Middle-travel,0.5mm,50mA,12V DC,–40~＋90℃,1.96N,SMT,ALPS; Manufacturer: ALPS; Myir P/N: 21201.00008; Part Type: Key; Datasheet: Connector\Key_ALPS_skra.pdf
U40 = RX-8025T: IC,I2C-Bus Interface RTC Module,SMD,SOP14,Epson; Manufacturer: Epson; Myir P/N: 20108.00003; Part Type: Clock; RP1 Manufacturer P/N: XCRSE8025TIAD; RP1 Myir P/N: 20108.80003; Datasheet: RX-8025T.pdf
U42 = AT9555PW: IC,16-bit I2C-bus I/O port with interrupt,TSSOP24,Novosense; Manufacturer: Novosense; Myir P/N: 20703.80023; Part Type: Interface; Datasheet: NCA9555.pdf

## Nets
DVDD_RGMII1: C209.1 C210.1 R346.1 R347.1 R368.1 R369.1 R371.1 U33.29(DVDD_RGMII)
DVDD_RGMII2: C228.1 C229.1 R381.1 R382.1 R403.1 R404.1 R406.1 U37.29(DVDD_RGMII)
GND: C138.2 C139.2 C140.2 C141.2 C142.2 C143.2 C144.2 C145.2 C146.2 C147.2 C148.2 C149.2 C150.2 C151.2 C152.2 C153.2 C154.2 C155.2 C156.2 C157.2 C158.2 C159.2 C160.2 C161.2 C162.2 C163.2 C164.2 C165.1 C166.2 C167.2 C168.2 C169.2 C170.1 C201.2 C202.2 C203.2 C204.2 C205.2 C206.2 C207.2 C208.2 C209.2 C210.2 C211.2 C212.2 C213.2 C214.2 C215.2 C216.2 C217.2 C218.2 C219.2 C220.2 C221.2 C222.2 C223.2 C224.2 C225.2 C226.2 C227.2 C228.2 C229.2 C230.2 C231.2 C232.2 C233.2 C234.2 C235.2 C236.2 C237.2 C238.2 C239.2 C240.2 C241.2 C242.2 C247.2 C248.2 C249.2 C250.2 C251.2 C253.2 D22.1 D23.1 D24.1 D25.1 D26.1 D27.1 D28.1 D29.1 D30.1 D40.1 D41.1 D42.1 D43.1 D45.1 D47.1 D49.1 D50.2(K) J15.A1(GND1) J15.A12(GND2) J15.B1(GND4) J15.B12(GND3) J16.A4(GND) J16.B4(GND) J25.2 Q5.2(S) R25.2 R26.2 R302.2 R307.2 R313.2 R320.1 R321.2 R362.2 R366.2 R367.2 R372.2 R373.2 R374.2 R375.2 R376.2 R377.2 R378.2 R397.2 R401.2 R402.2 R407.2 R408.2 R409.2 R410.2 R411.2 R412.2 R413.2 R419.2 R574.2 R575.2 S1.1 S1.2 S2.1 S2.2 S3.1 S3.2 U28.1(OVCB2) U28.5(OVCB3) U28.6(VSS) U28.7(OVCB4) U28.8(PWRB4) U28.10(VS_PLL) U28.16(VSS) U28.22(VSS) U28.25(VS_A) U28.33(VSS) U29.10(GND) U30.2(GND) U32.2(GND) U33.38(HSIP) U33.39(HSIN) U33.49(GND) U34.2(GND) U35.3(GND) U36.2(GND) U37.38(HSIP) U37.39(HSIN) U37.49(GND) U38.2(GND) U39.3(GND) U40.4(NC) U40.8(NC) U40.9(NC) U40.11(GND) U40.14(NC) U42.2(A1) U42.3(A2) U42.12(GND) U42.21(A0) Y3.2(GND/NC) Y3.4(GND/NC) Y4.2(GND/NC) Y4.4(GND/NC) Y5.2(GND/NC) Y5.4(GND/NC) ; also on sheet 1 2 6 7 8 9 10 11 12 13 14 15 16 22 23 24 25
GND_EARTH: C165.2 C170.2 C204.1 C223.1 J15.SH1 J15.SH2 J15.SH3 J15.SH4 J15.SH5 J15.SH6 J16.1(BODY1) J16.2(BODY2) J16.3(BODY3) J16.4(BODY4) J22.15(GND1) J22.16(GND2) J23.15(GND1) J23.16(GND2) R320.2 R321.1 R574.1 R575.1 ; also on sheet 6 14 23 25
VDD_3V3: C139.1 C140.1 C141.1 C142.1 C143.1 C144.1 C145.1 C153.1 C208.1 C227.1 C253.1 D48.2(NC) FB8.1 FB9.1 FB11.1 FB12.1 R300.1 R301.1 R303.2 R304.1 R305.1 R306.1 R308.1 R309.1 R310.1 R311.1 R312.1 R316.1 R318.1 R344.1 R345.1 R360.1 R361.1 R363.1 R379.1 R380.1 R395.1 R396.1 R398.1 R414.1 R416.1 R417.1 R423.1 R424.1 R426.1 R427.1 R428.1 R429.1 R431.1 R432.1 R434.1 R435.1 R437.1 R438.1 R456.1 R460.1 R467.1 R468.1 R470.1 R471.1 R473.1 R474.1 R498.1 R539.1 U28.13(VD33) U28.19(VD33) U28.27(VD3_IN) U28.32(VD33) U28.41(VD33) U29.12(VDD) U35.5(VCC) U39.5(VCC) U42.24(VCC) ; also on sheet 1 2 7 8 10 11 12 13 14 16 25
VDD_5V: C157.1 C159.1 F2.2 F3.2 U30.5(IN) ; also on sheet 1 2 7 12 13 14 24
VDD_BAT: D48.1(ANODE) J25.1
VDD_PHY1_1V1: C206.1 C207.1 C211.1 FB10.1 L11.2 U33.22(DVDDL)
VDD_PHY1_3V3: C214.1 C215.1 C216.1 FB9.2 R364.1 R365.1 R370.1 U33.30(DVDD33) U33.31(VDD33_LX)
VDD_PHY2_1V1: C225.1 C226.1 C230.1 FB13.1 L12.2 U37.22(DVDDL)
VDD_PHY2_3V3: C233.1 C234.1 C235.1 FB12.2 R399.1 R400.1 R405.1 U37.30(DVDD33) U37.31(VDD33_LX)
VDD_RTC: C249.1 C250.1 C251.1 D48.3(CATHODE) U40.6(VDD)
VDD_USB0_VBUS: C154.1 C155.1 C156.1 C161.1 C162.1 C163.1 C164.1 D22.2 J15.A4(VBUS1) J15.A9(VBUS2) J15.B4(VBUS4) J15.B9(VBUS3) U29.4(VBUS_DET) U30.1(OUT)
VDD_USB_1V8: C148.1 C149.1 C150.1 C151.1 C152.1 FB7.1 U28.3(VD18) U28.26(VREG18) U28.29(VD18)
VDD_USB_PLL: FB7.2 U28.9(VD_PLL)
VDDA_PHY1_1V1: C217.1 C218.1 C219.1 FB10.2 U33.4(AVDDL) U33.9(AVDDL) U33.47(AVDDL)
VDDA_PHY1_3V3: C212.1 C213.1 FB8.2 U33.1(AVDD33) U33.12(AVDD33)
VDDA_PHY2_1V1: C236.1 C237.1 C238.1 FB13.2 U37.4(AVDDL) U37.9(AVDDL) U37.47(AVDDL)
VDDA_PHY2_3V3: C231.1 C232.1 FB11.2 U37.1(AVDD33) U37.12(AVDD33)
AUDIO_I2C_SCL: R290.2 R434.2 ; also on sheet 16
AUDIO_I2C_SDA: R291.2 R435.2 ; also on sheet 16
BT_RST: U42.7(P03) ; also on sheet 10
ETH1_CONFIG_LDO0: R365.2 R367.1 U33.36(LED1/CFG_LDO0)
ETH1_LED_ACT: D41.2 J22.12(YELLOW-) R370.2 R373.1 U33.35(LED0/PHYAD0)
ETH1_LED_LINK: D40.2 J22.14(GREEN-) R364.2 R366.1 U33.37(LED2/CFG_LDO1)
ETH1_MD1_N: J22.2(TD1-) U32.6(D1-) U33.3(TRXN0)
ETH1_MD1_P: J22.1(TD1+) U32.1(D1+) U33.2(TPXP0)
ETH1_MD2_N: J22.4(TD2-) U32.4(D2-) U33.6(TRXN1)
ETH1_MD2_P: J22.3(TD2+) U32.3(D2+) U33.5(TRXP1)
ETH1_MD3_N: J22.8(TD3-) U33.8(TRXN2) U34.6(D1-)
ETH1_MD3_P: J22.7(TD3+) U33.7(TRXP2) U34.1(D1+)
ETH1_MD4_N: J22.10(TD4-) U33.11(TRXN3) U34.4(D2-)
ETH1_MD4_P: J22.9(TD4+) U33.10(TRXP3) U34.3(D2+)
ETH1_MRSTn: R361.2 U35.1(B) U42.9(P05)
ETH1_RST: R25.1 R363.2 U33.13(RESET_N) U35.4(Y)
ETH1_XTAl_I: C201.1 U33.45(XTAL_I) Y4.1
ETH1_XTAl_O: C205.1 U33.46(XTAL_O/EXT_CLK) Y4.3
ETH2_CONFIG_LDO0: R400.2 R402.1 U37.36(LED1/CFG_LDO0)
ETH2_LED_ACT: D43.2 J23.12(YELLOW-) R405.2 R408.1 U37.35(LED0/PHYAD0)
ETH2_LED_LINK: D42.2 J23.14(GREEN-) R399.2 R401.1 U37.37(LED2/CFG_LDO1)
ETH2_MD1_N: J23.2(TD1-) U36.6(D1-) U37.3(TRXN0)
ETH2_MD1_P: J23.1(TD1+) U36.1(D1+) U37.2(TPXP0)
ETH2_MD2_N: J23.4(TD2-) U36.4(D2-) U37.6(TRXN1)
ETH2_MD2_P: J23.3(TD2+) U36.3(D2+) U37.5(TRXP1)
ETH2_MD3_N: J23.8(TD3-) U37.8(TRXN2) U38.6(D1-)
ETH2_MD3_P: J23.7(TD3+) U37.7(TRXP2) U38.1(D1+)
ETH2_MD4_N: J23.10(TD4-) U37.11(TRXN3) U38.4(D2-)
ETH2_MD4_P: J23.9(TD4+) U37.10(TRXP3) U38.3(D2+)
ETH2_MRSTn: R396.2 U39.1(B) U42.10(P06)
ETH2_RST: R26.1 R398.2 U37.13(RESET_N) U39.4(Y)
ETH2_XTAl_I: C220.1 U37.45(XTAL_I) Y5.1
ETH2_XTAl_O: C224.1 U37.46(XTAL_O/EXT_CLK) Y5.3
I2C_SCL_CSI: R428.2 R452.2 ; also on sheet 13
I2C_SDA_CSI: R429.2 R444.2 ; also on sheet 13
LCD_I2C_SCL: R431.2 R445.2 ; also on sheet 14
LCD_I2C_SDA: R432.2 R489.2 ; also on sheet 14
LCD_TP_INTn: U42.4(P00) ; also on sheet 14
LCD_TP_RESET: U42.5(P01) ; also on sheet 14
LVDS0_I2C_SCL: R438.2 R491.2 ; also on sheet 12
LVDS0_I2C_SDA: R437.2 R449.2 ; also on sheet 12
LVDS1_I2C_SCL: R451.2 R467.2 ; also on sheet 12
LVDS1_I2C_SDA: R468.2 R492.2 ; also on sheet 12
RTC_I2C_SCL: R453.2 R470.2 U40.2(SCL)
RTC_I2C_SDA: R471.2 R493.2 U40.13(SDA)
SoC_EXTINT_GPIO1_31: R498.2 U42.1(INT_N) ; also on sheet 22
SoC_GPMC0_BE1n: C247.1 C248.1 D49.2 R417.2 S3.3 S3.4 ; also on sheet 22
SoC_I2C1_SCL: R192.1 ; also on sheet 22
SoC_I2C1_SCL_R: R460.2 R461.2 U42.22(SCL)
SoC_I2C1_SDA: R141.1 R449.1 ; also on sheet 22
SoC_I2C1_SDA_R: R141.2 R456.2 U42.23(SDA)
SoC_MCU_MCAN1_RX: D53.2(K) ; also on sheet 22
SoC_MCU_RESETz: C240.1 D44.1 R414.2 ; also on sheet 22
SoC_MMC2_SDCD: R308.2 U29.6(INTB/OUT3) ; also on sheet 22
SoC_PORz_OUT: U35.2(A) U39.2(A) ; also on sheet 22
SoC_RESET_REQz: C242.1 D46.1 R416.2 ; also on sheet 22
SoC_RGMII1_RD0: R358.2 ; also on sheet 22
SoC_RGMII1_RD0_R: R358.1 R371.2 R372.1 U33.26(RXD0/RXDLY)
SoC_RGMII1_RD1: R356.2 ; also on sheet 22
SoC_RGMII1_RD1_R: R356.1 R376.1 U33.25(RXD1/CFG_MODE0)
SoC_RGMII1_RD2: R357.2 ; also on sheet 22
SoC_RGMII1_RD2_R: R357.1 R377.1 U33.24(RXD2/CFG_MODE1)
SoC_RGMII1_RD3: R359.2 ; also on sheet 22
SoC_RGMII1_RD3_R: R359.1 R378.1 U33.23(RXD3/CFG_MODE2)
SoC_RGMII1_RX_CTL: R355.2 ; also on sheet 22
SoC_RGMII1_RXC: R354.2 ; also on sheet 22
SoC_RGMII1_RXC_R: R354.1 R369.2 R374.1 U33.28(RX_CLK/PHYAD1)
SoC_RGMII1_RXCTL_R: R355.1 R368.2 R375.1 U33.27(RX_DV/PHYAD2)
SoC_RGMII1_TD0: R352.2 ; also on sheet 22
SoC_RGMII1_TD0_R: R352.1 U33.19(TXD0)
SoC_RGMII1_TD1: R350.2 ; also on sheet 22
SoC_RGMII1_TD1_R: R350.1 U33.18(TXD1)
SoC_RGMII1_TD2: R351.2 ; also on sheet 22
SoC_RGMII1_TD2_R: R351.1 U33.17(TXD2)
SoC_RGMII1_TD3: R353.2 ; also on sheet 22
SoC_RGMII1_TD3_R: R353.1 U33.16(TXD3)
SoC_RGMII1_TX_CTL: R349.2 ; also on sheet 22
SoC_RGMII1_TXC: R348.2 ; also on sheet 22
SoC_RGMII1_TXC_R: R348.1 U33.21(TX_CLK)
SoC_RGMII1_TXCTL_R: R349.1 U33.20(TX_CTL)
SoC_RGMII2_RD0: R391.2 ; also on sheet 22
SoC_RGMII2_RD0_R: R391.1 R406.2 R407.1 U37.26(RXD0/RXDLY)
SoC_RGMII2_RD1: R392.2 ; also on sheet 22
SoC_RGMII2_RD1_R: R392.1 R411.1 U37.25(RXD1/CFG_MODE0)
SoC_RGMII2_RD2: R393.2 ; also on sheet 22
SoC_RGMII2_RD2_R: R393.1 R412.1 U37.24(RXD2/CFG_MODE1)
SoC_RGMII2_RD3: R394.2 ; also on sheet 22
SoC_RGMII2_RD3_R: R394.1 R413.1 U37.23(RXD3/CFG_MODE2)
SoC_RGMII2_RX_CTL: R390.2 ; also on sheet 22
SoC_RGMII2_RXC: R389.2 ; also on sheet 22
SoC_RGMII2_RXC_R: R389.1 R404.2 R409.1 U37.28(RX_CLK/PHYAD1)
SoC_RGMII2_RXCTL_R: R390.1 R403.2 R410.1 U37.27(RX_DV/PHYAD2)
SoC_RGMII2_TD0: R383.2 ; also on sheet 22
SoC_RGMII2_TD0_R: R383.1 U37.19(TXD0)
SoC_RGMII2_TD1: R388.2 ; also on sheet 22
SoC_RGMII2_TD1_R: R388.1 U37.18(TXD1)
SoC_RGMII2_TD2: R384.2 ; also on sheet 22
SoC_RGMII2_TD2_R: R384.1 U37.17(TXD2)
SoC_RGMII2_TD3: R385.2 ; also on sheet 22
SoC_RGMII2_TD3_R: R385.1 U37.16(TXD3)
SoC_RGMII2_TX_CTL: R387.2 ; also on sheet 22
SoC_RGMII2_TXC: R386.2 ; also on sheet 22
SoC_RGMII2_TXC_R: R386.1 U37.21(TX_CLK)
SoC_RGMII2_TXCTL_R: R387.1 U37.20(TX_CTL)
SoC_RGMII_MDC: R381.2 R542.1 U37.14(MDC) ; also on sheet 22
SoC_RGMII_MDIO: R382.2 R543.1 U37.15(MDIO) ; also on sheet 22
SoC_UART0_CTSn: R554.1 ; also on sheet 22
SoC_UART0_RTSn: R492.1 R493.1 R494.1 ; also on sheet 22
SoC_UART1_DCDn: R142.1 ; also on sheet 22
SoC_UART1_DSRn: R291.1 R444.1 R489.1 ; also on sheet 22
SoC_USB0_DM: L9.1 ; also on sheet 22
SoC_USB0_DP: L9.4 ; also on sheet 22
SoC_USB0_DRVVBUS: R317.2 ; also on sheet 22
SoC_USB1_DM: U28.30(DMU) ; also on sheet 22
SoC_USB1_DP: U28.31(DPU) ; also on sheet 22
USB0CC1: C158.1 R314.1 U29.1(CC1)
USB0CC2: C160.1 R315.1 U29.2(CC2)
USB_5G_DM: U28.17(DM3) ; also on sheet 24
USB_5G_DP: U28.18(DP3) ; also on sheet 24
USB_HUB_RST: R487.1 U42.6(P02)
USB_I2C_SCL: R454.2 R473.2 U29.8(SCL/OUT2)
USB_I2C_SDA: R474.2 R494.2 U29.7(SDA/OUT1)
USBA0_DM: D27.2 J16.A2(USBHMA) U28.20(DM2)
USBA0_DP: D28.2 J16.A3(USBHPA) U28.21(DP2)
USBA1_DM: D30.2 J16.B2(USBHMB) U28.23(DM1)
USBA1_DP: D29.2 J16.B3(USBHPB) U28.24(DP1)
USBC_ID: R309.2 R319.1 U29.9(ID)
USER_LED: D54.2(K) U42.8(P04)
WWAN_LED_n: D55.2(K) ; also on sheet 24
N21392930: L11.1 U33.32(LX)
N21392969: R346.2 R542.2 U33.14(MDC)
N21392972: R347.2 R543.2 U33.15(MDIO)
N21393016: R360.2 U33.34(INT_N/PME_N)
N21393026: R362.1 U33.48(RBIAS)
N21393171: C202.1 C203.1 J22.5(CT1) J22.6(CT2)
N21405925: L12.1 U37.32(LX)
N21406011: R395.2 U37.34(INT_N/PME_N)
N21406021: R397.1 U37.48(RBIAS)
N21406166: C221.1 C222.1 J23.5(CT1) J23.6(CT2)
N21473108: C147.1 U28.11(XOUT) Y3.1
N21476694: C146.1 U28.12(XIN) Y3.3
N21477956: R306.2 R487.2 U28.34(XRSTJ)
N21670486: C239.1 D44.2 D45.2 S1.3 S1.4
N21676766: C241.1 D46.2 D47.2 S2.3 S2.4
N21848668: C138.1 U28.38(VD5_IN)
N21848671: R302.1 U28.40(TEST)
N21849105: R300.2 U28.48(OVCB1)
N21849965: R301.2 U28.39(VD33_OUT)
N22324946: D23.2 J15.A6(DP1) J15.B6(DP2) L9.3
N22324958: D24.2 J15.A7(DN1) J15.B7(DN2) L9.2
N22324997: R310.2 U29.5(ADR/CON_DET)
N22325047: R311.2 U29.11(EXT_SEL(ENB))
N22325067: R312.2 R313.1 U29.3(PORT)
N22325125: D25.2 J15.A5(CC1) R314.2
N22325136: D26.2 J15.B5(CC2) R315.2
N22325338: Q5.3(D) R316.2 R317.1 U30.4(EN)
N22325344: R318.2 U30.3(~{FLAG})
N22325474: Q5.1(G) R319.2
N22325526: C166.1 C167.1 F2.1 J16.A1(VCC)
N22325538: C168.1 C169.1 F3.1 J16.B1(VCC) TP14.1(TP)
N22407725: D55.1(A) R427.2
N22517589: J22.11(YELLOW+) R344.2
N22517591: J22.13(GREEN+) R345.2
N22525013: J23.13(GREEN+) R380.2
N22525015: J23.11(YELLOW+) R379.2
N22597309: R192.2 R461.1 R491.1
N22610391: R539.2 U40.10(nINT)
N22863110: R142.2 R290.1 R445.1 R452.1
N22863348: R451.1 R453.1 R454.1 R554.2
N22973519: R419.1 U40.7(FOE)
N23945057: D50.1(A) R423.2
N24701406: R307.1 U28.28(REXT)
N24701492: R305.2 U28.35(VBUSM)
N24701498: R304.2 U28.36(BUS_B)
N24701504: R303.1 U28.37(DIS_REG)
N25609213: D53.1(A) R424.2
N25609260: D54.1(A) R426.2

Not connected (* = marked no-connect by the designer): J15 A2(SSTXP1) A3(SSTXN1) A8(SBU1) A10(SSRXN2) A11(SSRXP2) B2(SSTXP2) B3(SSTXN2) B8(SBU2) B10(SSRXN1) B11(SSRXP1); U28 2(PWRB2) 4(PWRB3) 14(DM4) 15(DP4) 42(DRV) 43(LED1) 44(LED2) 45(LED3) 46(LED4) 47(PWRB1); U32 5(NC); U33 33(RESERVED2) 40(HSOP) 41(HSON) 42(NC) 43(RESERVED1) 44(CLKOUT); U34 5(NC); U36 5(NC); U37 33(RESERVED2) 40(HSOP) 41(HSON) 42(NC) 43(RESERVED1) 44(CLKOUT); U38 5(NC); U40 1(T1) 3(FOUT) 5(TEST) 12(T2); U42 11(P07) 13(P10) 14(P11) 15(P12) 16(P13) 17(P14) 18(P15) 19(P16) 20(P17)

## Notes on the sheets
sheet 17
- USB2.0 Hub
- USB-C (OTG/DRP)
- GPIO0_71
- Low = DFP(host) mode detected valid UFP(device)
  on CC1 or CC2 line.
- Dual Ports USB-A Host
sheet 18
- CPSW RGMII 1 - PHY
- R137 near U37 side
- R138,R139,R141,R143 near U37 side
- R147 near U34 side
- R148,R149,R150,R151 near U34 side
- Switch regulator 1.1V output
- Default 10K pull-down on SOM
- 1
- DVDD33
- Power
- Description
- Digital non-RGMII IO Power.3.3V
- 2'b00
- CFG_LDO[1:0]
- External 3.3V
- Voltage Selection
- 0
- VDD_REG
- 3.3V Power for Switching Regulator
- 2'b01
- Internal 2.5V
- Select 1.8V
- DVDD_RG
- Digital RGMII I/O,MDIO,MDC Pad Power
- 2'b10
- Internal 1.8V
- REG_OUT
- Switching Regulator 1.0V Output.Connect to a 2.2uH inductor.
- 2'b11
- Not Available
- PHYAD2
- 1
- RXD[3:1]
- Operation Mode
- PHYAD1
- 0
- 3'b000
- UTP <=> RGMII
- PHYAD0
- 1
- 3'b001
- FIBER <=> RGMII
- RXC Delay Enable
- 3'b010
- 3'b011
- UTP <=> SGMII
- UTP/FIBER <=> RGMII
- 3'b100
- SGMII (PHY) <=> RGMII
- 3'b101
- SGMII (MAC) <=> RGMII
- 3'b110
- UTP <=> FIBER (AUTO)
- 3'b111
- UTP <=> FIBER (FORCE)
- When connect an external 25MHz oscillator or clock from another device to XTAL_I pin,keep the XTAL_O floating.
  When connect an external 25MHz oscillator or clock from another device to XTAL_O pin,XTAL_I must be shorted to GND.
- If RESET, LED0, CFG_LDO[1:0] need to be pulled up,they should be pulled up to DVDD33.
- If RXD[3:0], RX_CLK, RX_DV need to be pulled pulled up,they should be pulled up to DVDD_RGMII.
- If the LED pin is pulled high,it will be an active low output. And if the LED pin is pulled low,it will be an active high output
sheet 19
- CPSW RGMII 2 - PHY
- R137 near U37 side
- R138,R139,R141,R143 near U37 side
- R147 near U34 side
- R148,R149,R150,R151 near U34 side
- Switch regulator 1.1V output
- Default 10K pull-down on SOM
- 1
- Power
- Description
- CFG_LDO[1:0]
- Voltage Selection
- 0
- DVDD33
- VDD_REG
- 3.3V Power for Switching Regulator
- Digital non-RGMII IO Power.3.3V
- 2'b00
- 2'b01
- External 3.3V
- Internal 2.5V
- Select 1.8V
- DVDD_RG
- Digital RGMII I/O,MDIO,MDC Pad Power
- 2'b10
- Internal 1.8V
- REG_OUT
- Switching Regulator 1.0V Output.Connect to a 2.2uH inductor.
- 2'b11
- Not Available
- PHYAD2
- 0
- RXD[3:1]
- Operation Mode
- PHYAD1
- 0
- 3'b000
- UTP <=> RGMII
- PHYAD0
- 1
- 3'b001
- FIBER <=> RGMII
- RXC Delay Enable
- 3'b010
- UTP/FIBER <=> RGMII
- 3'b011
- 3'b100
- SGMII (PHY) <=> RGMII
- UTP <=> SGMII
- 3'b101
- SGMII (MAC) <=> RGMII
- 3'b110
- UTP <=> FIBER (AUTO)
- 3'b111
- UTP <=> FIBER (FORCE)
- When connect an external 25MHz oscillator or clock from another device to XTAL_I pin,keep the XTAL_O floating.
  When connect an external 25MHz oscillator or clock from another device to XTAL_O pin,XTAL_I must be shorted to GND.
- If RESET, LED0, CFG_LDO[1:0] need to be pulled up,they should be pulled up to DVDD33.
- If RXD[3:0], RX_CLK, RX_DV need to be pulled pulled up,they should be pulled up to DVDD_RGMII.
- if the LED pin is pulled high,it will be an active low output. And if the LED pin is pulled low,it will be an active high output
sheet 20
- RTC
- MCU Reset Key
- SoC Reset Key
- LED
- Power Indicator
- System Run Indicator
- MCU_GPIO0_16
- User-defined Indicator
- User Key
- 4G/5G Status Indicator
sheet 21
- I2C IO Expander
- INTn output is activated when changes state and the pin is configured as an input.
  A pin configured as an output cannot cause an interrupt.
- I2C SHARE
- SoC_I2C0_SCL
- SoC_I2C0_SDA
- SoC_I2C3_SCL
- SoC_I2C3_SDA
- 22R Series resistors placed close to SOM connector.
  0R Series resistors placed in cross poin,close to slave device.
